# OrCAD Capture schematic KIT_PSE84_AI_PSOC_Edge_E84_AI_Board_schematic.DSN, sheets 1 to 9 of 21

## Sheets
1 20. Accessories: title: PSOC™ Edge E84 AI Board; rev: 03; note: 630-60751-01
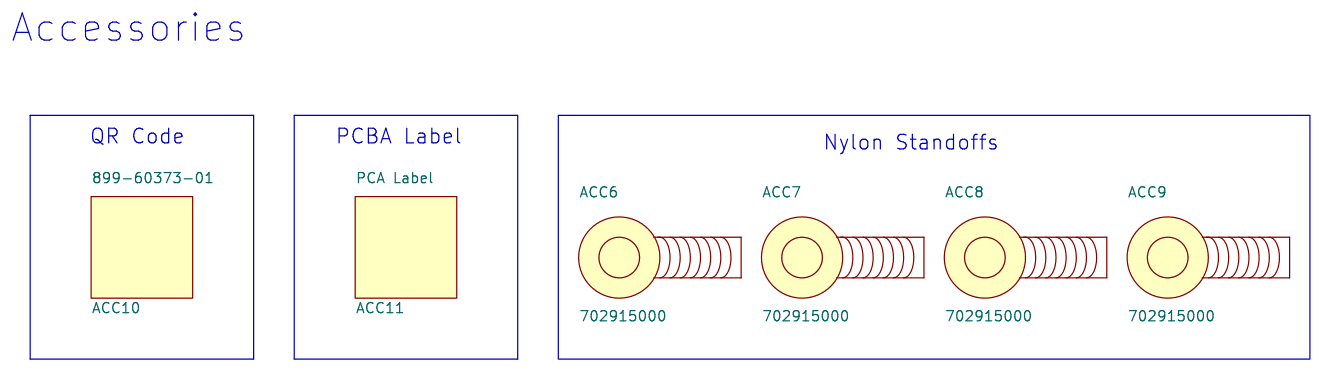
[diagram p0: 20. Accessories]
2 01. Title Page
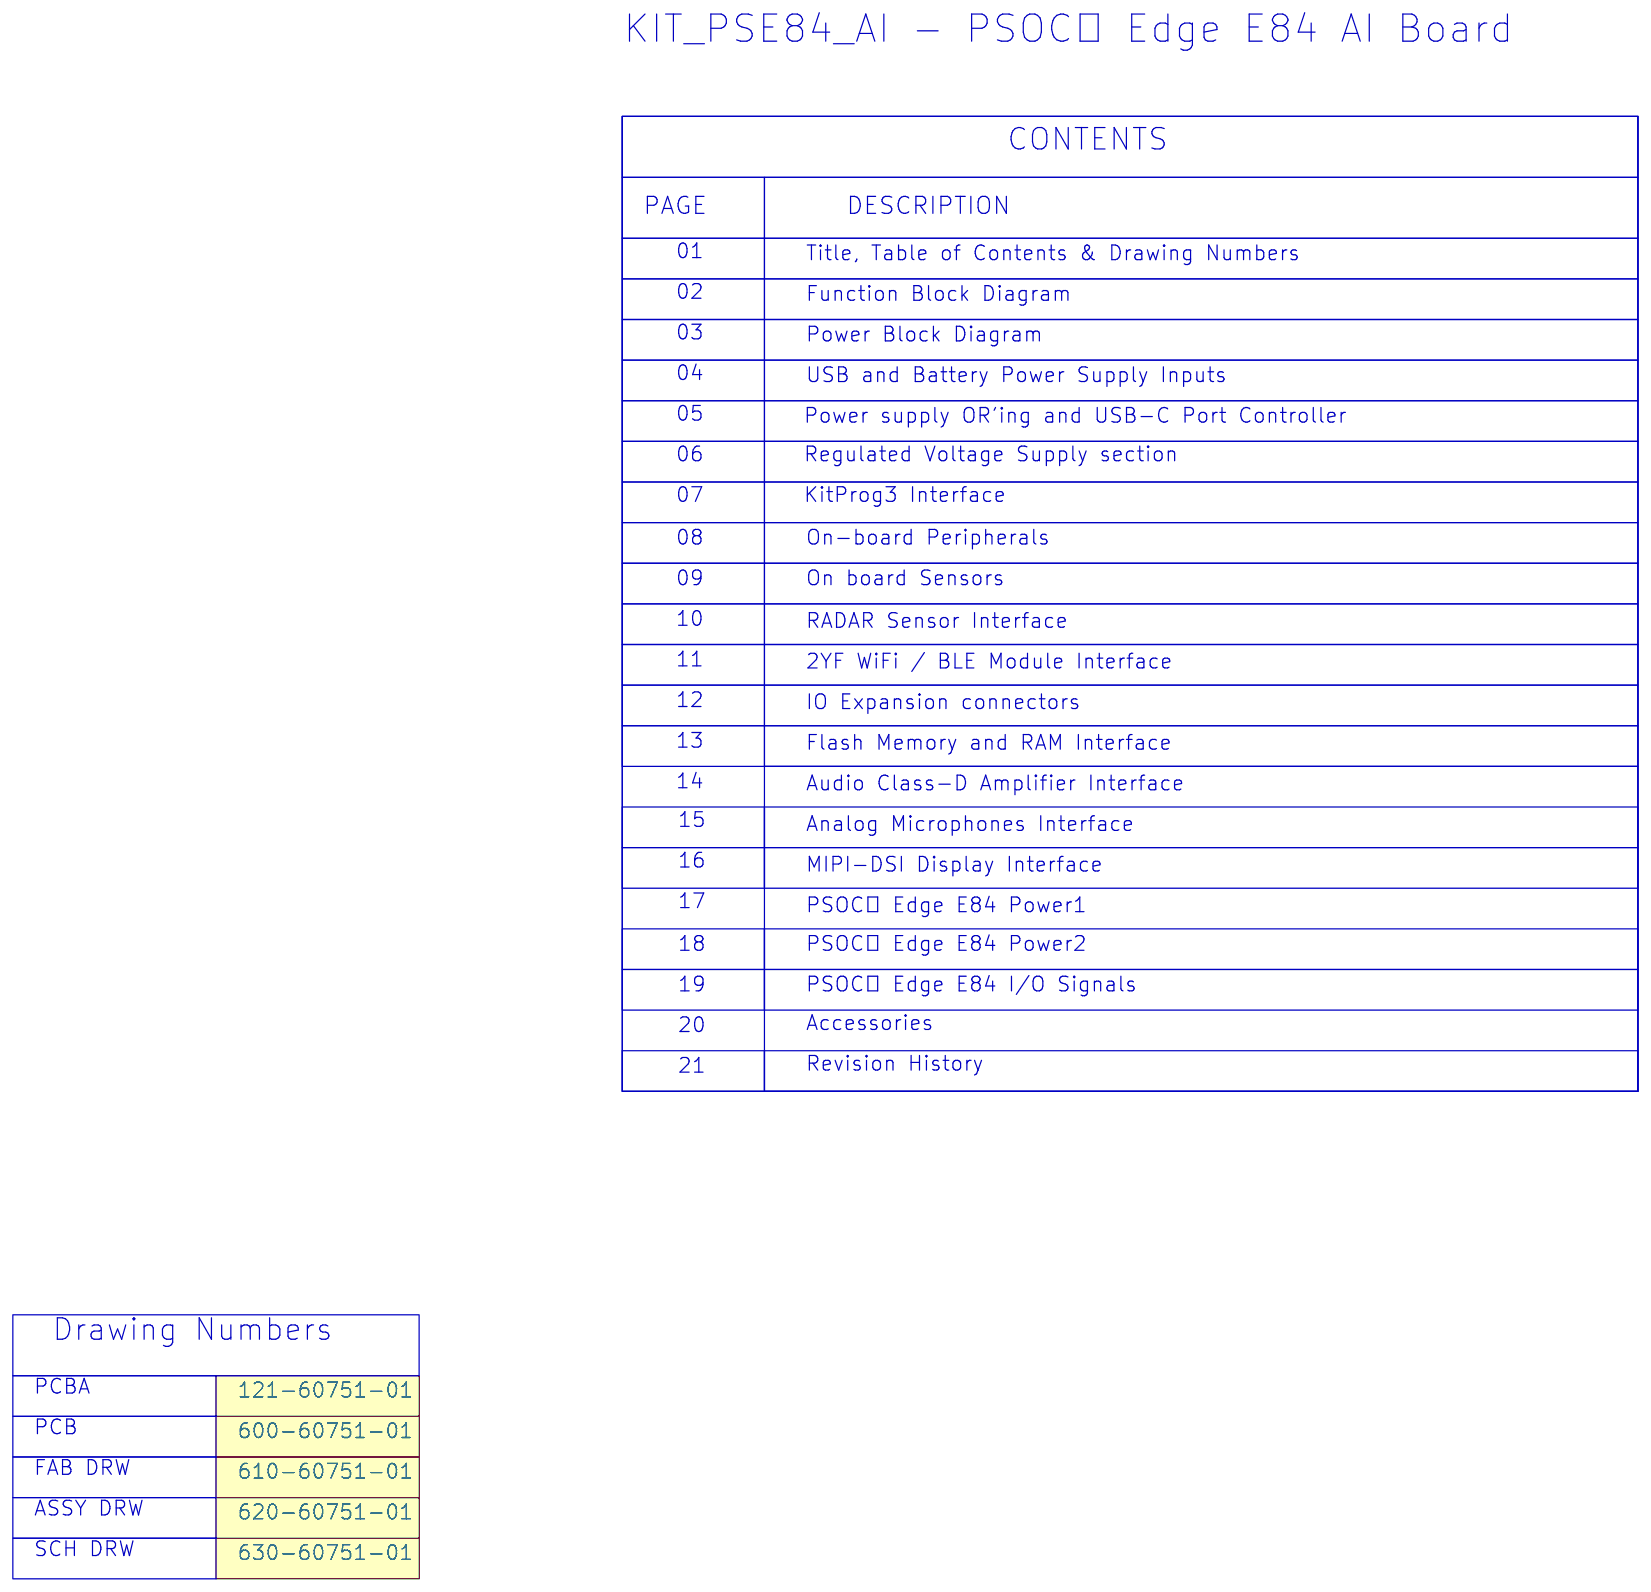
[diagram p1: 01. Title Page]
3 02. Functional Block Diagram
4 03. Power Block Diagram
5 05. Power Supply OR'ing: size A4
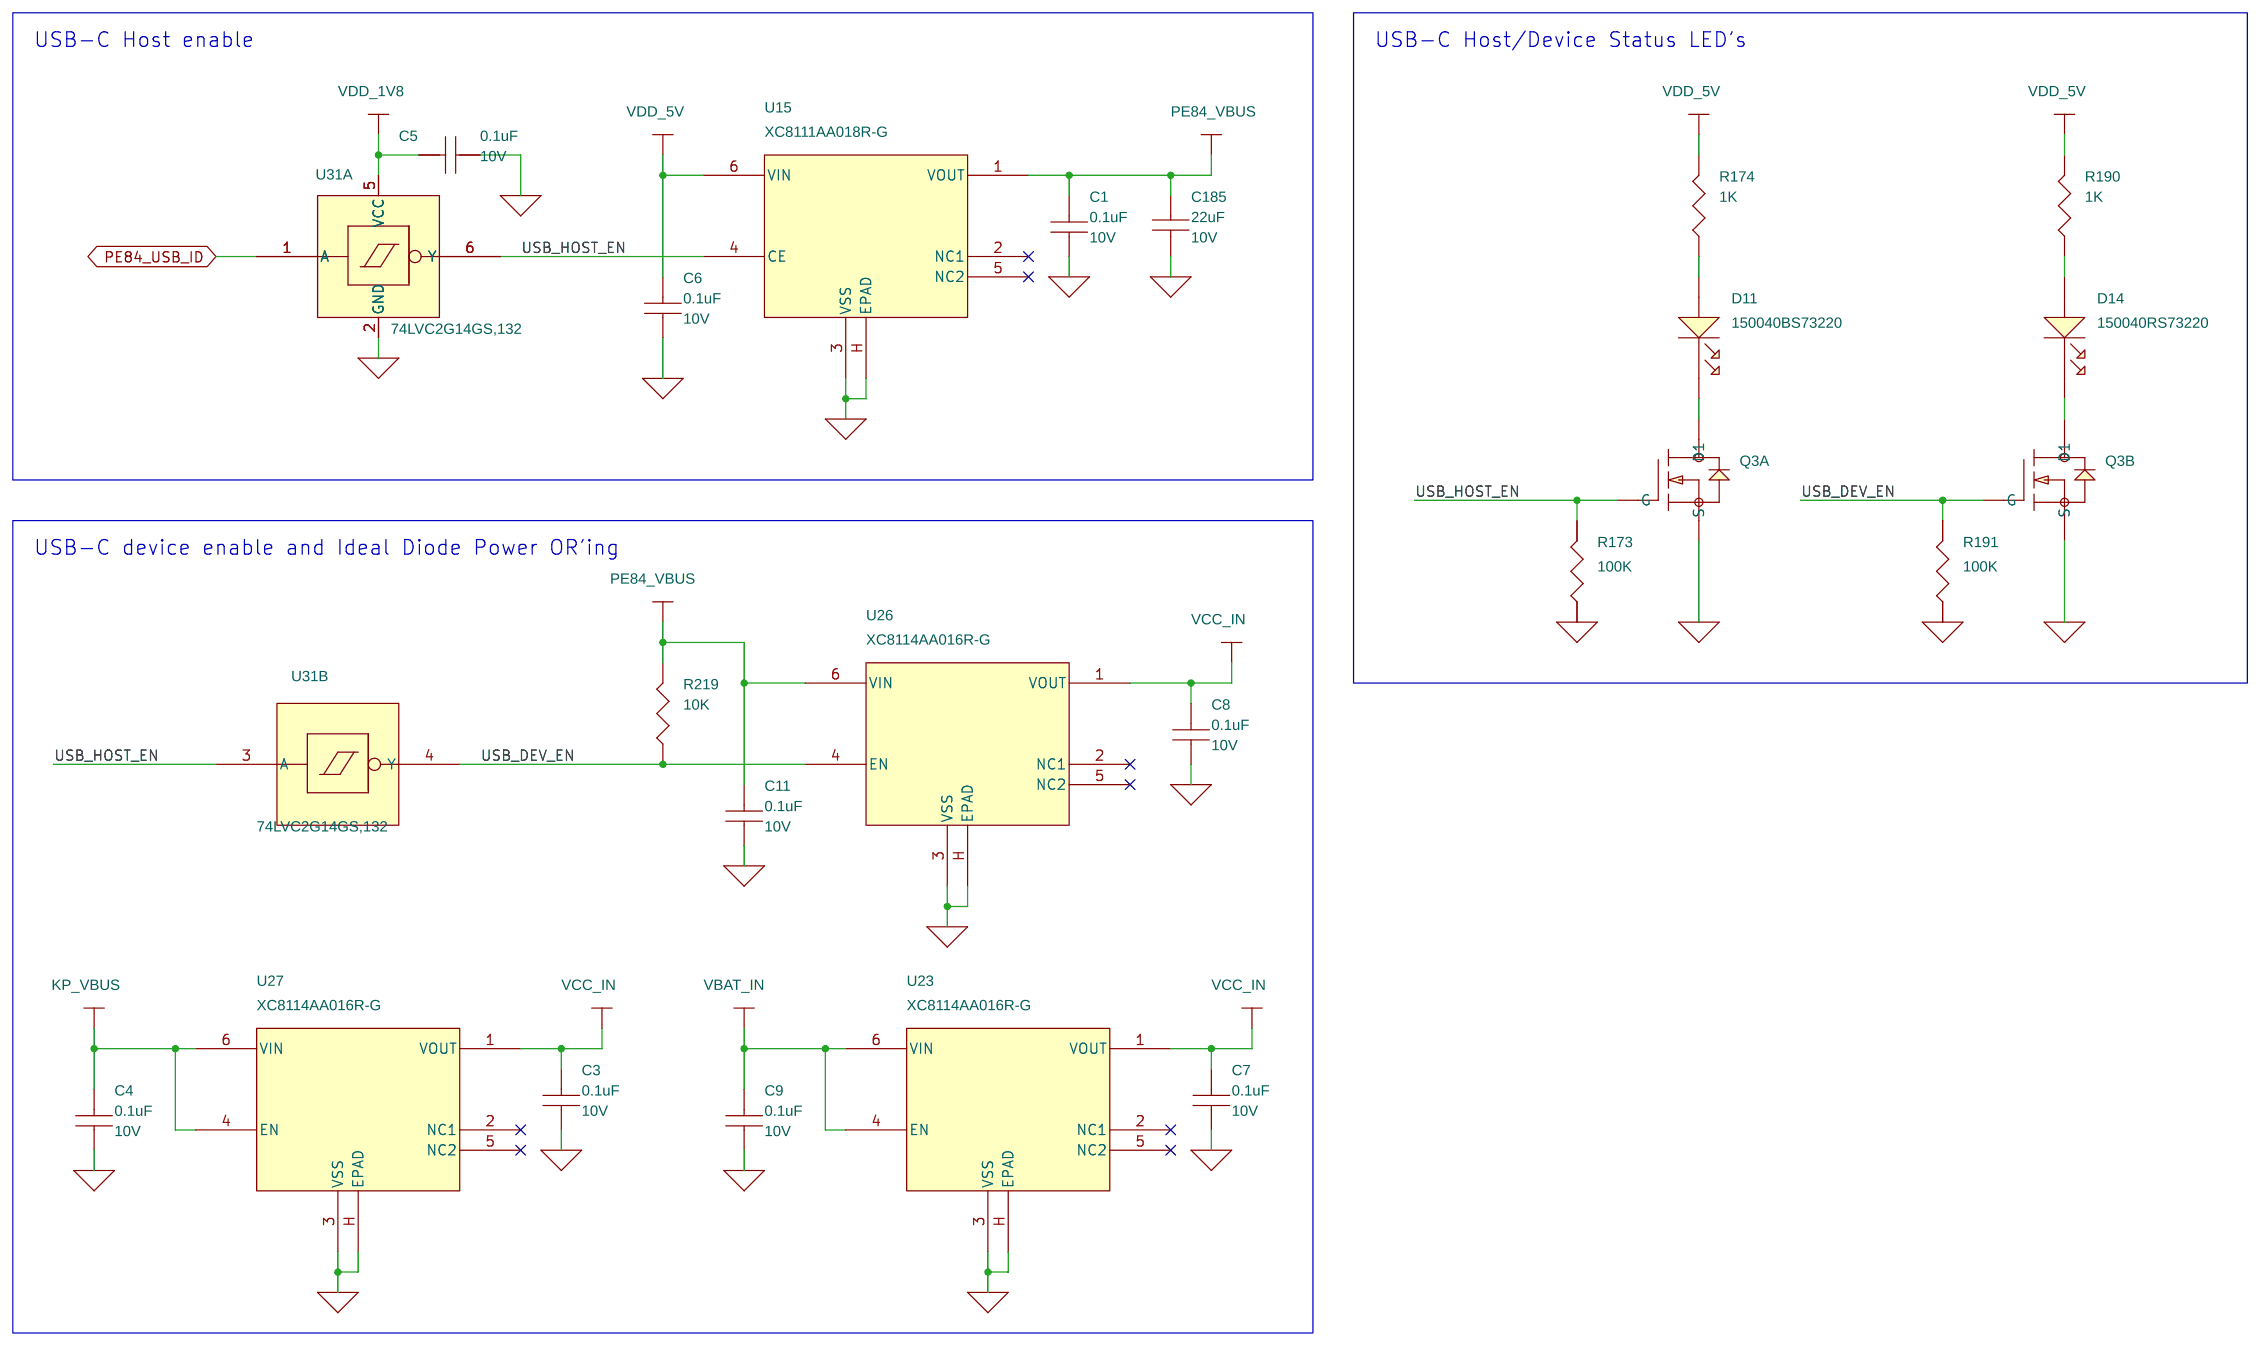
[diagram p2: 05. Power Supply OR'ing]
6 04. USB and Battery Pwr. Supply: size A4
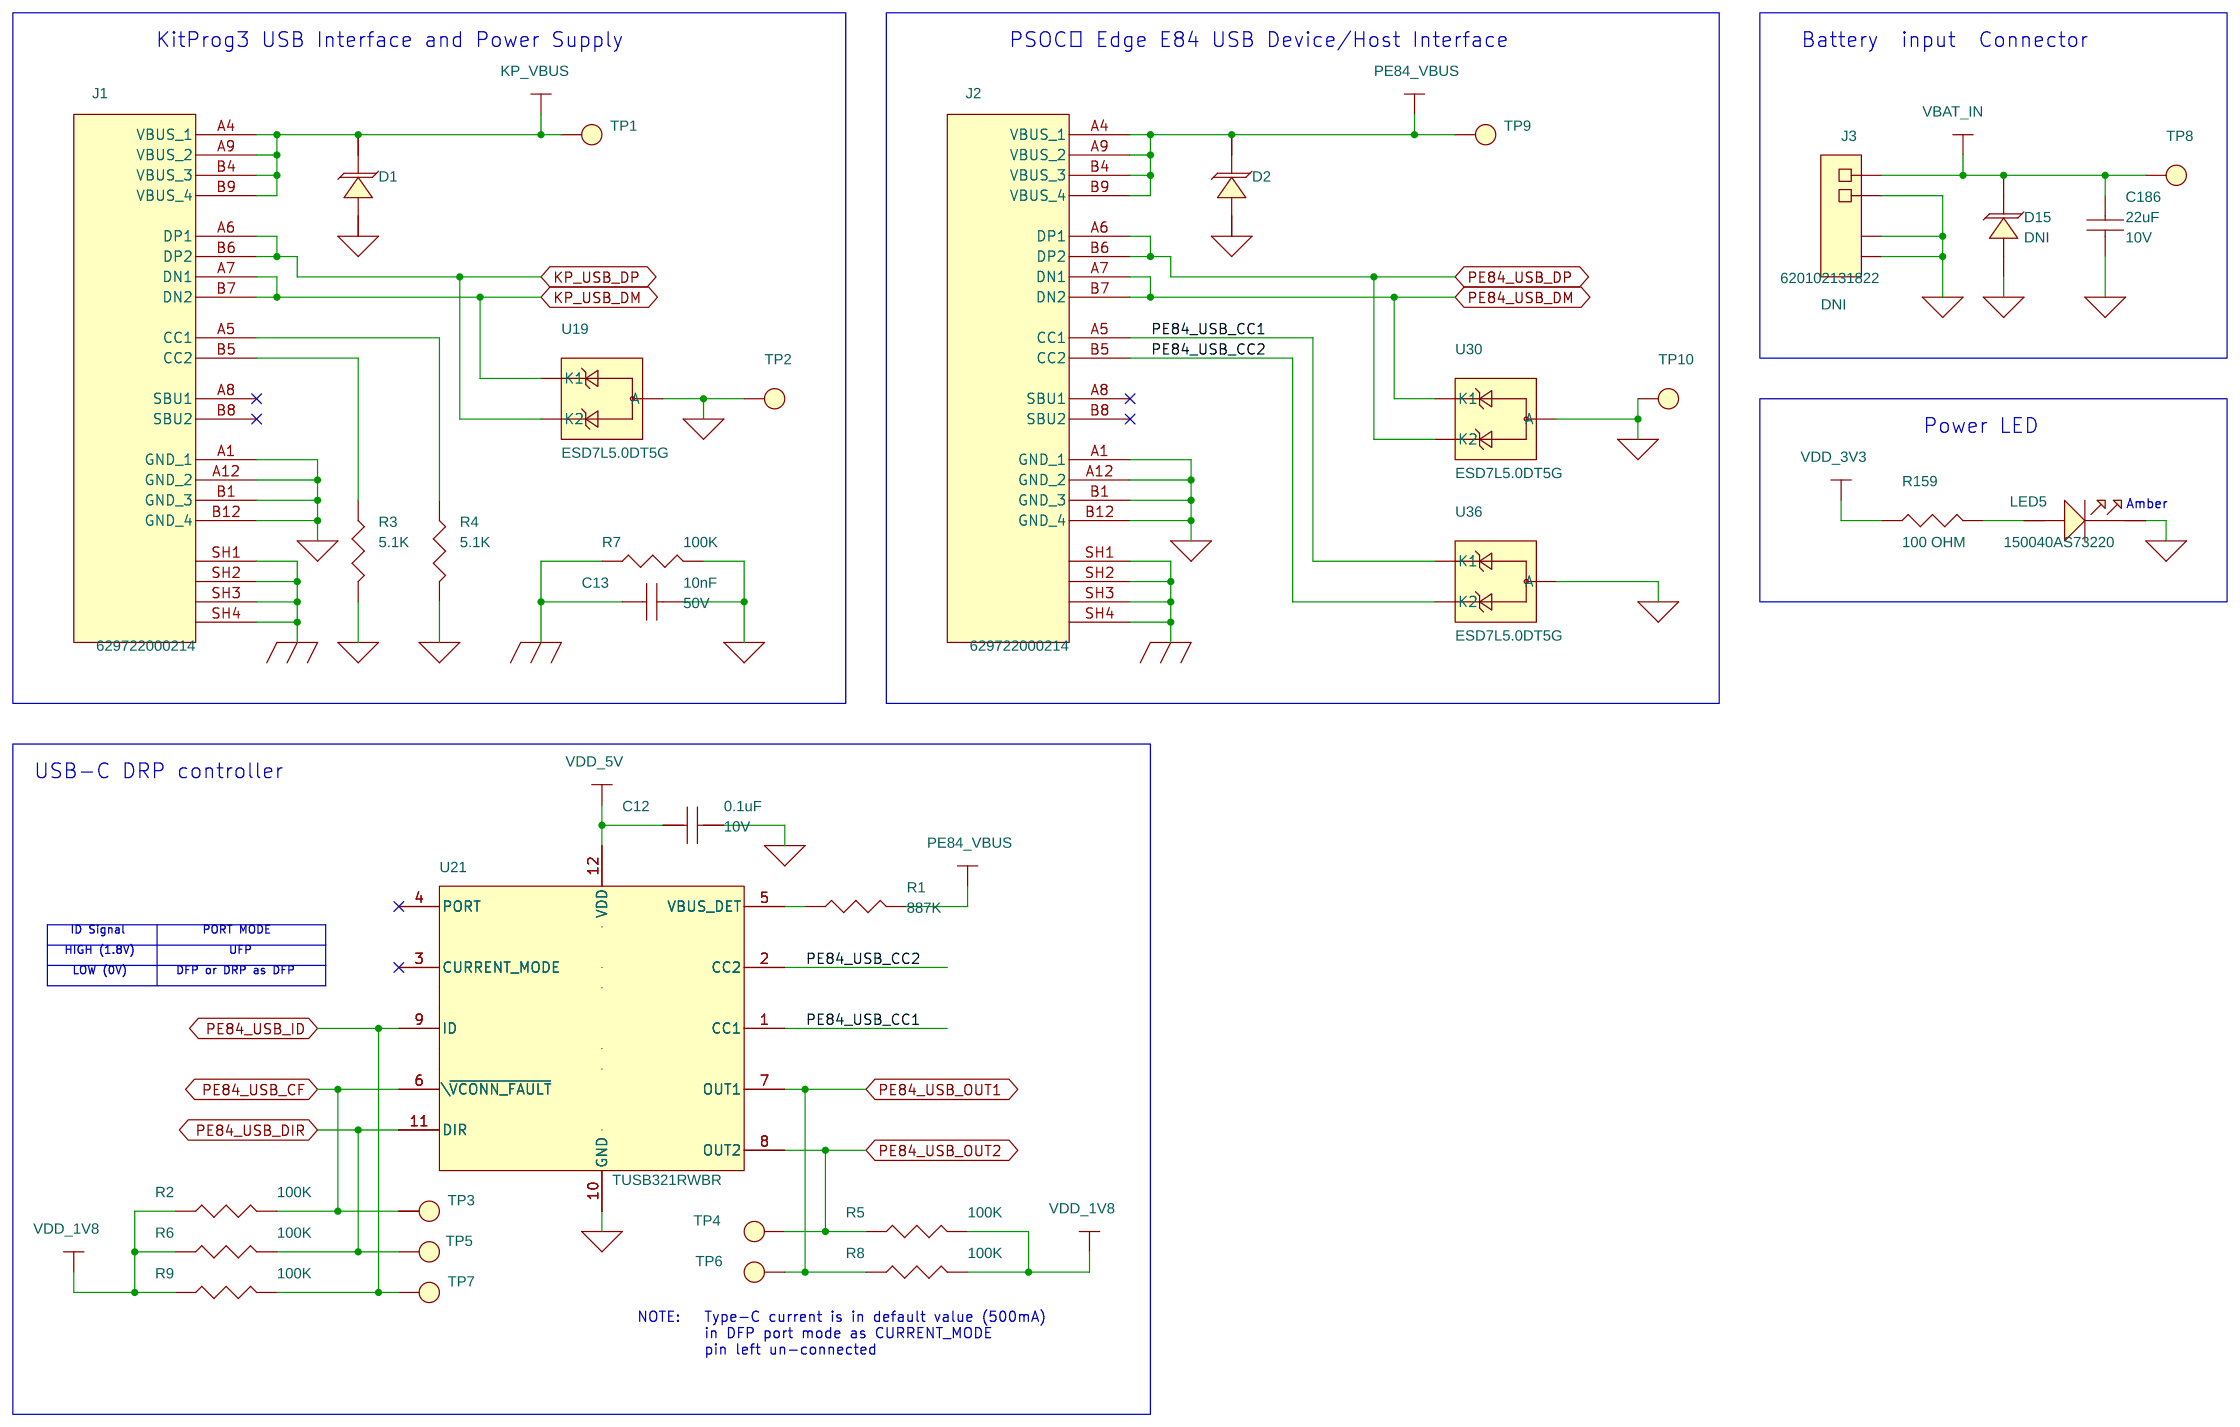
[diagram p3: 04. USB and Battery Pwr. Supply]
7 06. Regulated Voltage Supply: size A4
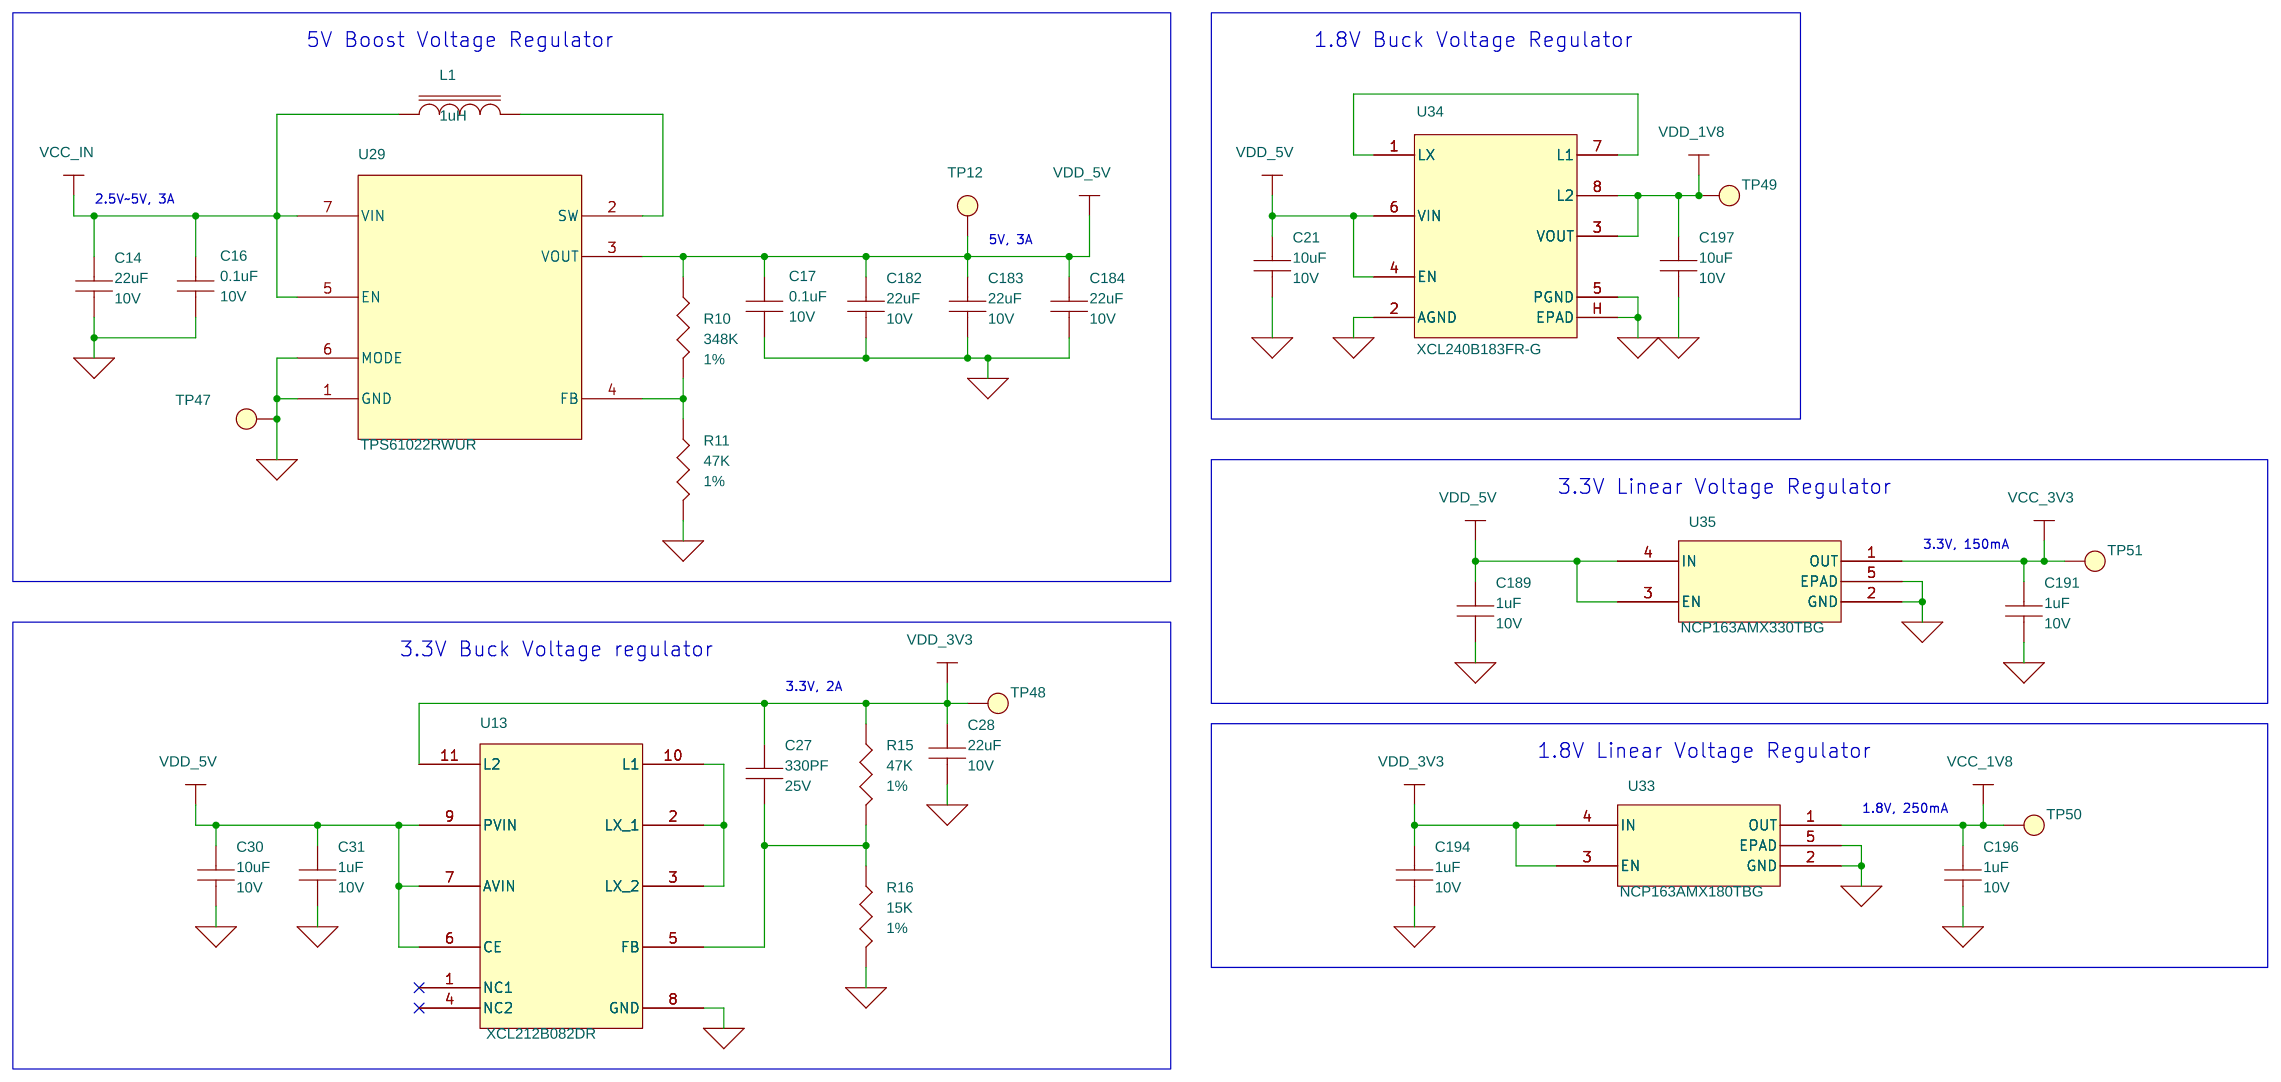
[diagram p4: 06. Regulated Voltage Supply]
8 07. KitProg3 Interface: size A4
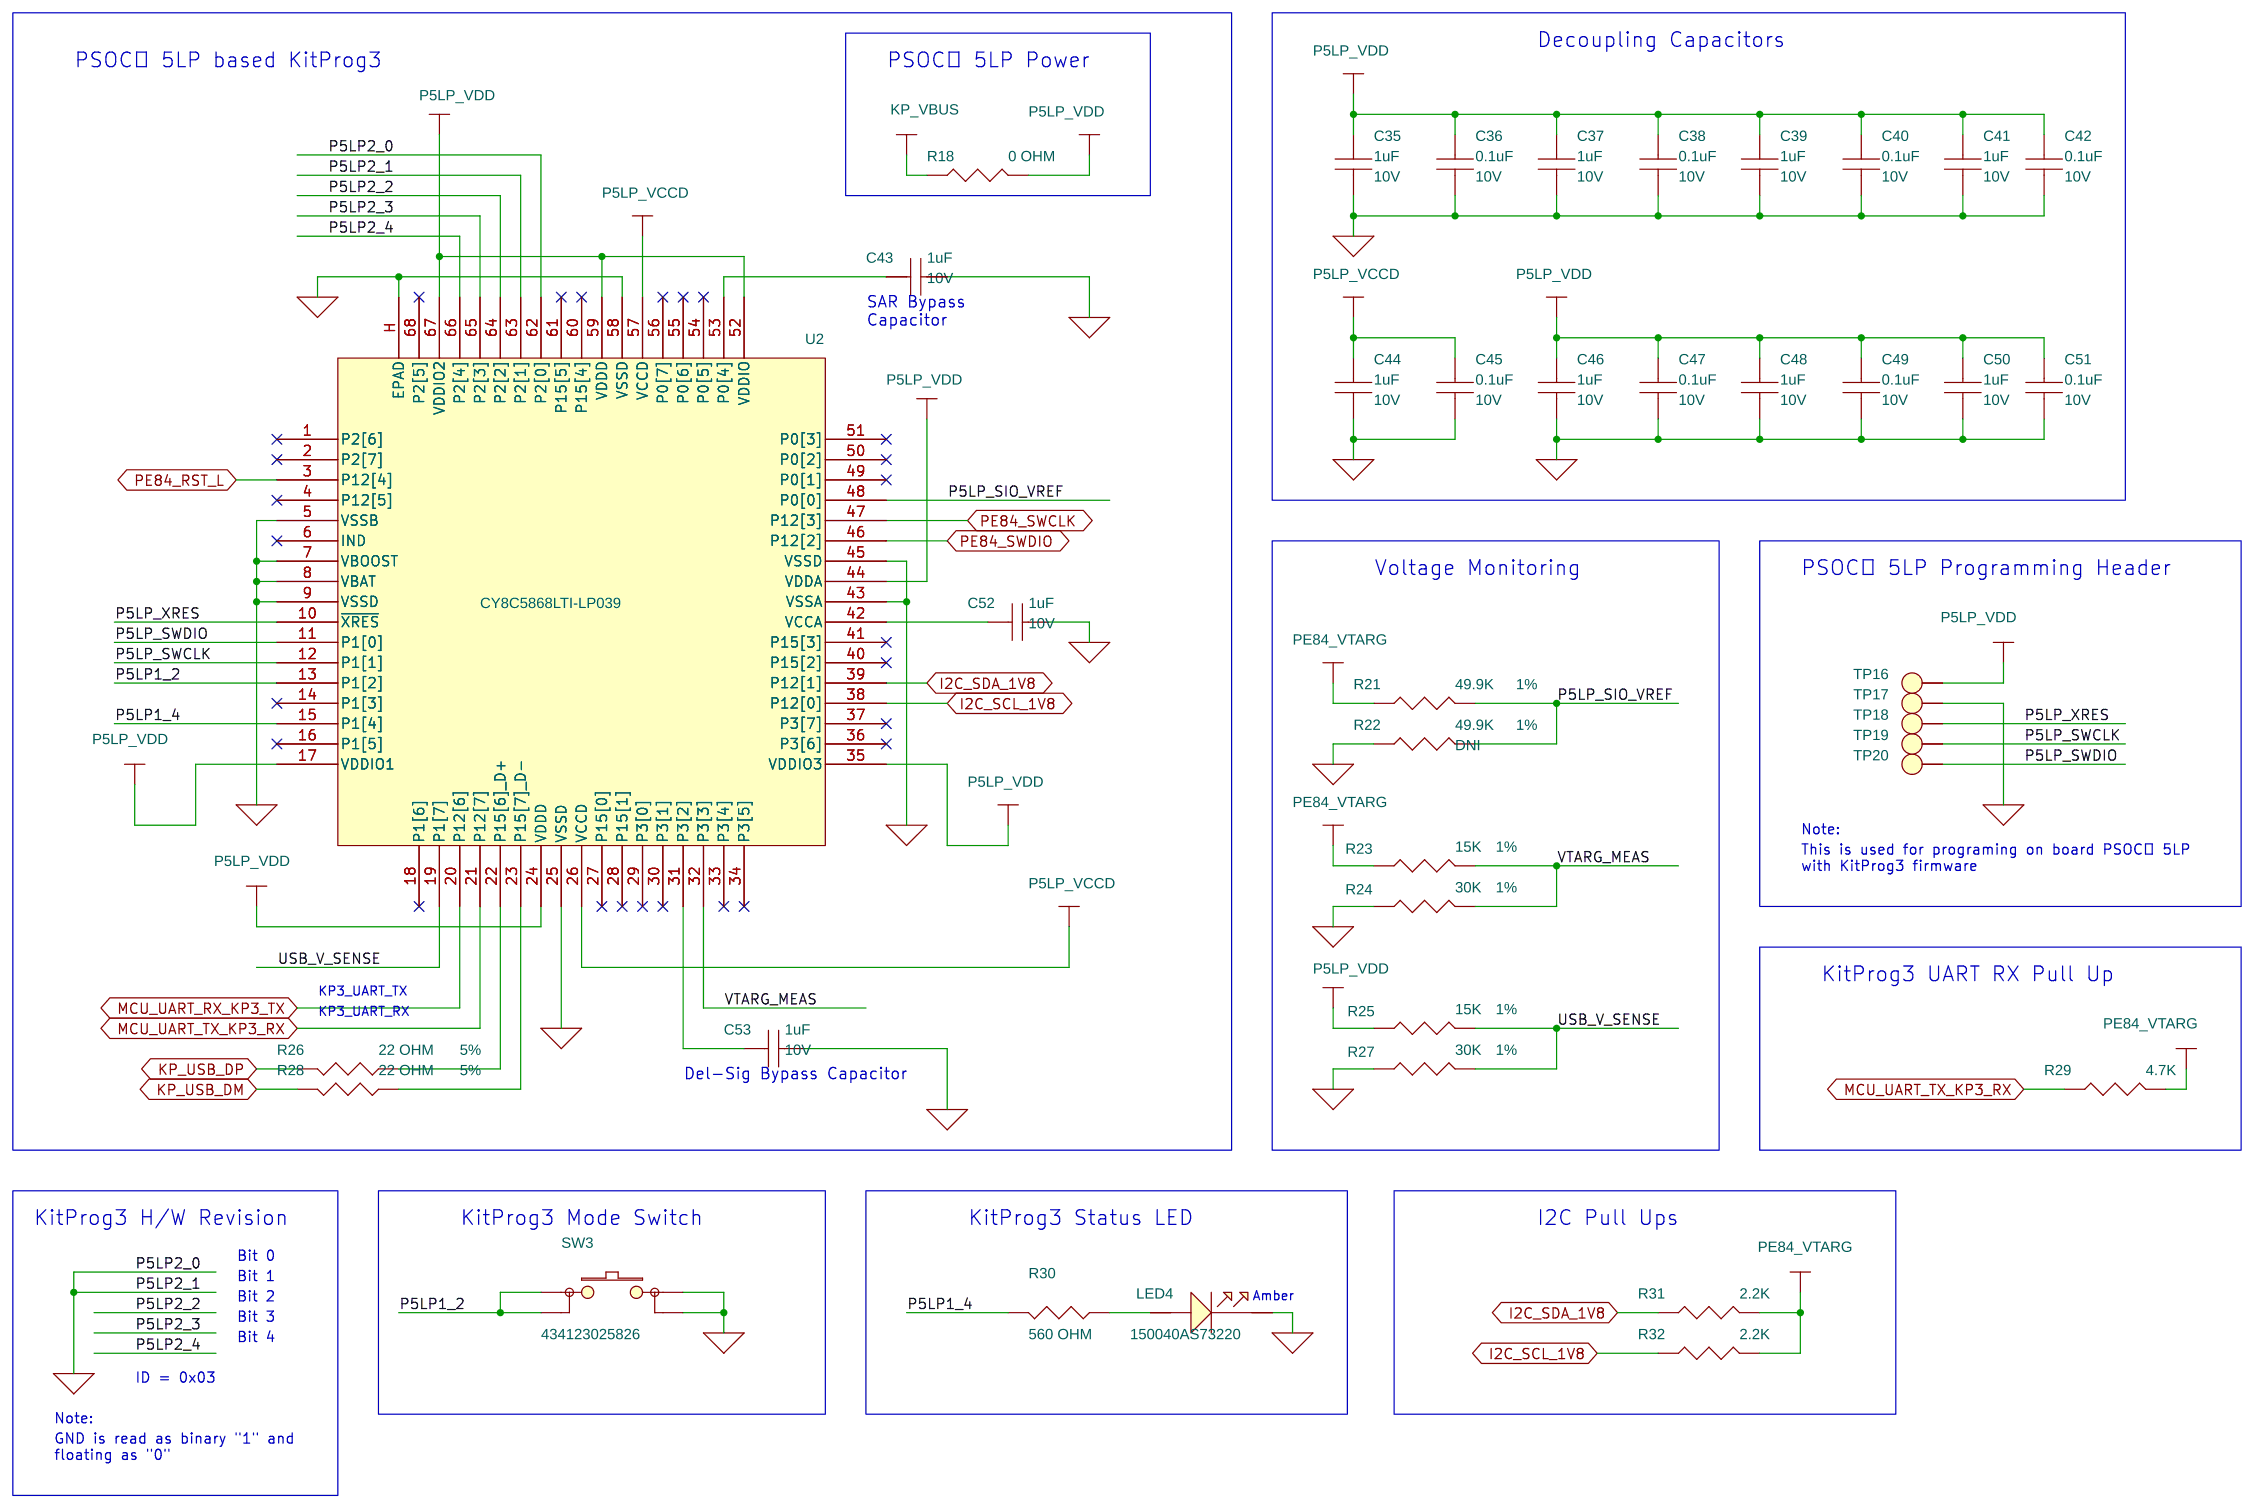
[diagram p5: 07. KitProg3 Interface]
9 08. On-Board Peripherals: size A4
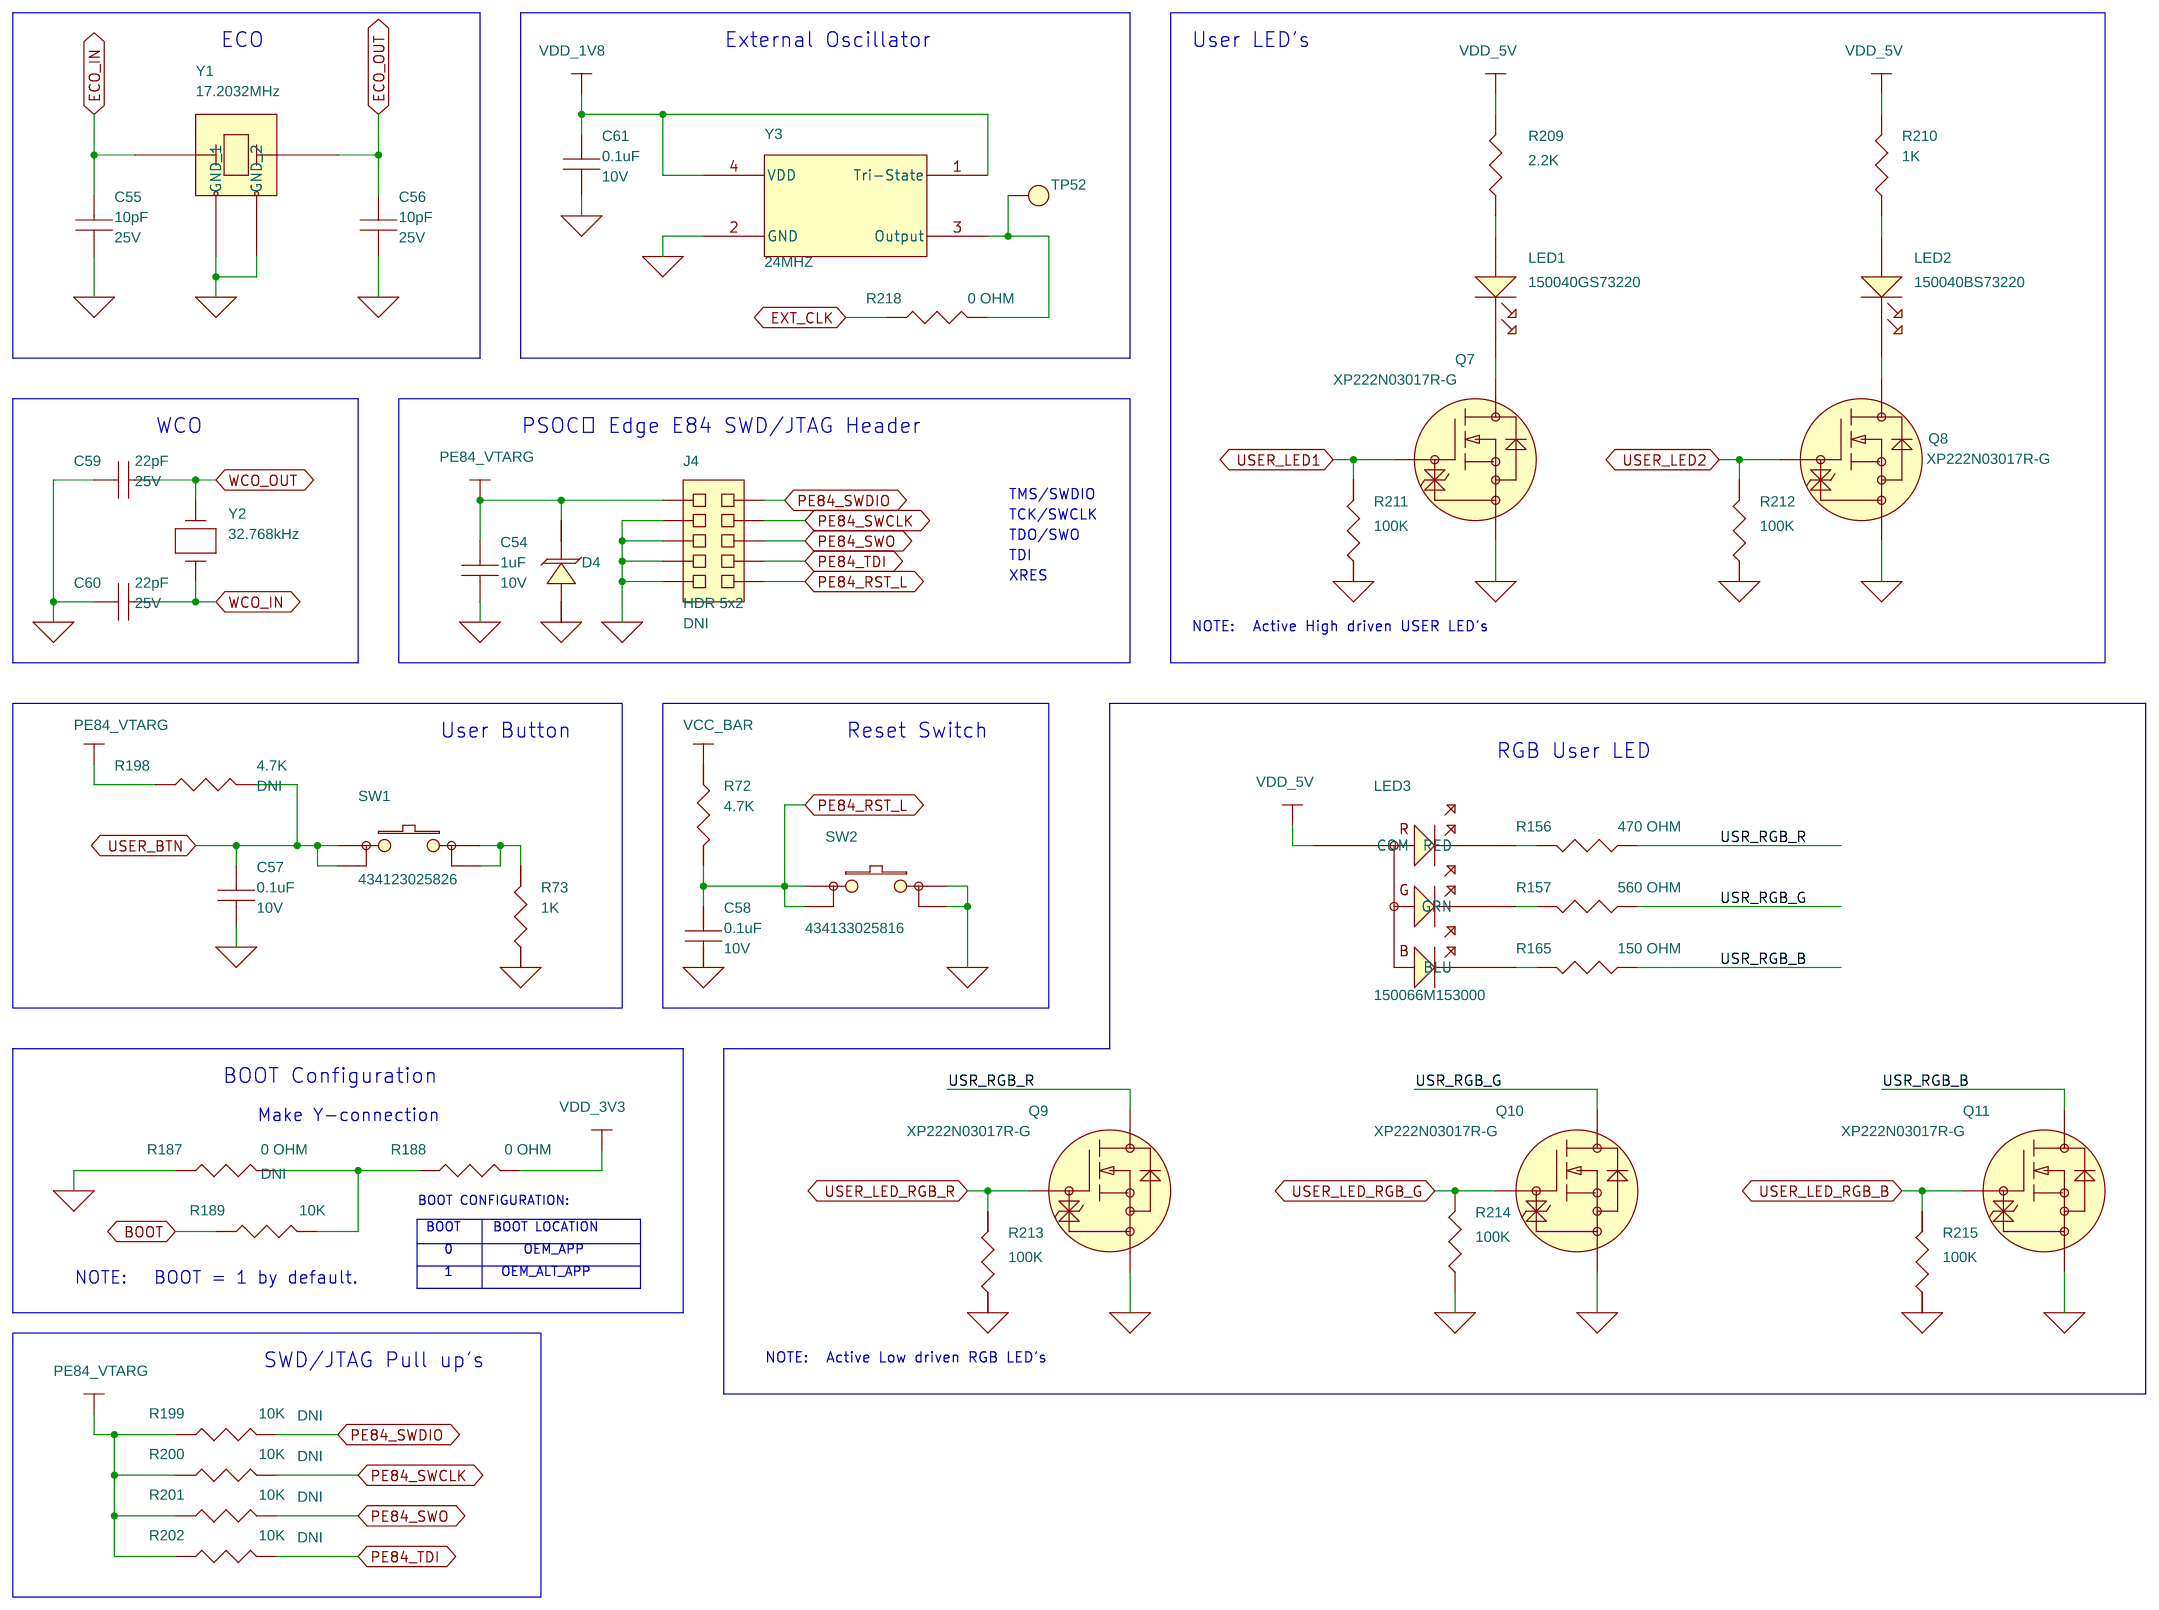
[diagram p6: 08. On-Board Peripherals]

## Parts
sheet 01. Title Page
ACC1  121-60751-01  [TBD]
ACC2  600-60751-01  [TBD]
ACC3  610-60751-01  [TBD]
ACC4  620-60751-01  [TBD]
ACC5  630-60751-01  [TBD]
sheet 04. USB and Battery Pwr. Supply
C12  0.1uF  [CAPC0603_0201N]
C13  10nF  [CAPC1005_0402N]
C186  22uF  [CAPC1005_0402N]
D1  T5V0S5A-7  [SODFL1608X77N]
D2  T5V0S5A-7  [SODFL1608X77N]
D15  T5V0S5A-7  [SODFL1608X77N]
J1  629722000214  [GCT_USB4105-GF-A]
J2  629722000214  [GCT_USB4105-GF-A]
J3  620102131822  [JST_S2B-PH-SM4-TB-LF-SN]
LED5  150040AS73220  [LEDC1005X35N_AMB_WURTH]
R1  887K  [RESC0603_0201N]
R2  100K  [RESC0603_0201N]
R3  5.1K  [RESC0603_0201N]
R4  5.1K  [RESC0603_0201N]
R5  100K  [RESC0603_0201N]
R6  100K  [RESC0603_0201N]
R7  100K  [RESC0603_0201N]
R8  100K  [RESC0603_0201N]
R9  100K  [RESC0603_0201N]
R159  100 OHM  [RESC0603_0201N]
TP1  TP_SMD  [ict_tp_smd_030rd_nsp]
TP2  TP_SMD  [ict_tp_smd_030rd_nsp]
TP3  TP_SMD  [ict_tp_smd_030rd_nsp]
TP4  TP_SMD  [ict_tp_smd_030rd_nsp]
TP5  TP_SMD  [ict_tp_smd_030rd_nsp]
TP6  TP_SMD  [ict_tp_smd_030rd_nsp]
TP7  TP_SMD  [ict_tp_smd_030rd_nsp]
TP8  TP_SMD  [ict_tp_smd_030rd_nsp]
TP9  TP_SMD  [ict_tp_smd_030rd_nsp]
TP10  TP_SMD  [ict_tp_smd_030rd_nsp]
U19  ESD7L5.0DT5G  [SOTFL40P120X59-3N]
U21  TUSB321RWBR  [X2QFN40P160X160X40-12N_TI]
U30  ESD7L5.0DT5G  [SOTFL40P120X59-3N]
U36  ESD7L5.0DT5G  [SOTFL40P120X59-3N]
sheet 05. Power Supply OR'ing
C1  0.1uF  [CAPC0603_0201N]
C3  0.1uF  [CAPC0603_0201N]
C4  0.1uF  [CAPC0603_0201N]
C5  0.1uF  [CAPC0603_0201N]
C6  0.1uF  [CAPC0603_0201N]
C7  0.1uF  [CAPC0603_0201N]
C8  0.1uF  [CAPC0603_0201N]
C9  0.1uF  [CAPC0603_0201N]
C11  0.1uF  [CAPC0603_0201N]
C185  22uF  [CAPC1005_0402N]
D11  150040BS73220  [LEDC1005X35N_AMB_WURTH]
D14  150040RS73220  [LEDC1005X35N_AMB_WURTH]
Q3  BSD840NH6327XTSA1  [SOT65P210X100-6M]  (sections A,B)
R173  100K  [RESC0603_0201N]
R174  1K  [RESC0603_0201N]
R190  1K  [RESC0603_0201N]
R191  100K  [RESC0603_0201N]
R219  10K  [RESC0603_0201N]
U15  XC8111AA018R-G  [XFDFN50P180X150X33-7N_TOREX]
U23  XC8114AA016R-G  [SON50P200X180X60-6N_TP]
U26  XC8114AA016R-G  [SON50P200X180X60-6N_TP]
U27  XC8114AA016R-G  [SON50P200X180X60-6N_TP]
U31  74LVC2G14GS,132  [DFN35P100X100X40-6N]  (sections A,B)
sheet 06. Regulated Voltage Supply
C14  22uF  [CAPC1005_0402N]
C16  0.1uF  [CAPC0603_0201N]
C17  0.1uF  [CAPC0603_0201N]
C21  10uF  [CAPC1005_0402N]
C27  330PF  [CAPC0603_0201N]
C28  22uF  [CAPC1005_0402N]
C30  10uF  [CAPC1005_0402N]
C31  1uF  [CAPC0603_0201N]
C182  22uF  [CAPC1005_0402N]
C183  22uF  [CAPC1005_0402N]
C184  22uF  [CAPC1005_0402N]
C189  1uF  [CAPC1005_0402N]
C191  1uF  [CAPC1005_0402N]
C194  1uF  [CAPC1005_0402N]
C196  1uF  [CAPC1005_0402N]
C197  10uF  [CAPC1005_0402N]
L1  1uH  [IND_74438336010]
R10  348K  [RESC0603_0201N]
R11  47K  [RESC0603_0201N]
R15  47K  [RESC0603_0201N]
R16  15K  [RESC0603_0201N]
TP12  TP_SMD  [ict_tp_smd_030rd_nsp]
TP47  TP_SMD  [ict_tp_smd_030rd_nsp]
TP48  TP_SMD  [ict_tp_smd_030rd_nsp]
TP49  TP_SMD  [ict_tp_smd_030rd_nsp]
TP50  TP_SMD  [ict_tp_smd_030rd_nsp]
TP51  TP_SMD  [ict_tp_smd_030rd_nsp]
U13  XCL212B082DR  [CONV_XCL212B082DR]
U29  TPS61022RWUR  [VQFN50P200X200X100-7N_TI]
U33  NCP163AMX180TBG  [DFN65P100X100X43-5N]
U34  XCL240B183FR-G  [CONV_XCL240B183FR-G]
U35  NCP163AMX330TBG  [DFN65P100X100X43-5N]
sheet 07. KitProg3 Interface
C35  1uF  [CAPC0603_0201N]
C36  0.1uF  [CAPC0603_0201N]
C37  1uF  [CAPC0603_0201N]
C38  0.1uF  [CAPC0603_0201N]
C39  1uF  [CAPC0603_0201N]
C40  0.1uF  [CAPC0603_0201N]
C41  1uF  [CAPC0603_0201N]
C42  0.1uF  [CAPC0603_0201N]
C43  1uF  [CAPC0603_0201N]
C44  1uF  [CAPC0603_0201N]
C45  0.1uF  [CAPC0603_0201N]
C46  1uF  [CAPC0603_0201N]
C47  0.1uF  [CAPC0603_0201N]
C48  1uF  [CAPC0603_0201N]
C49  0.1uF  [CAPC0603_0201N]
C50  1uF  [CAPC0603_0201N]
C51  0.1uF  [CAPC0603_0201N]
C52  1uF  [CAPC0603_0201N]
C53  1uF  [CAPC0603_0201N]
LED4  150040AS73220  [LEDC1005X35N_AMB_WURTH]
R18  0 OHM  [RESC1005_0402N]
R21  49.9K  [RESC0603_0201N]
R22  49.9K  [RESC0603_0201N]
R23  15K  [RESC0603_0201N]
R24  30K  [RESC0603_0201N]
R25  15K  [RESC0603_0201N]
R26  22 OHM  [RESC0603_0201N]
R27  30K  [RESC0603_0201N]
R28  22 OHM  [RESC0603_0201N]
R29  4.7K  [RESC0603_0201N]
R30  560 OHM  [RESC1005_0402N]
R31  2.2K  [RESC0603_0201N]
R32  2.2K  [RESC0603_0201N]
SW3  434123025826  [SW_SKRPACE010]
TP16  TP_SMD  [ict_tp_smd_030rd_nsp]
TP17  TP_SMD  [ict_tp_smd_030rd_nsp]
TP18  TP_SMD  [ict_tp_smd_030rd_nsp]
TP19  TP_SMD  [ict_tp_smd_030rd_nsp]
TP20  TP_SMD  [ict_tp_smd_030rd_nsp]
U2  CY8C5868LTI-LP039  [QFN40P800X800_68-H580N]
sheet 08. On-Board Peripherals
C54  1uF  [CAPC0603_0201N]
C55  10pF  [CAPC0603_0201N]
C56  10pF  [CAPC0603_0201N]
C57  0.1uF  [CAPC0603_0201N]
C58  0.1uF  [CAPC0603_0201N]
C59  22pF  [CAPC0603_0201N]
C60  22pF  [CAPC0603_0201N]
C61  0.1uF  [CAPC0603_0201N]
D4  ESD5V0D5-TP  [SODFL1608X77N]
J4  HDR 5x2  [SAMT_FTSH-105-XX-X-DV-K]
LED1  150040GS73220  [LEDC1005X35N_AMB_WURTH]
LED2  150040BS73220  [LEDC1005X35N_AMB_WURTH]
LED3  150066M153000  [LED_150066M153000]
Q7  XP222N03017R-G  [SOTFL40P120X50-3N_MOSFET_TOREX]
Q8  XP222N03017R-G  [SOTFL40P120X50-3N_MOSFET_TOREX]
Q9  XP222N03017R-G  [SOTFL40P120X50-3N_MOSFET_TOREX]
Q10  XP222N03017R-G  [SOTFL40P120X50-3N_MOSFET_TOREX]
Q11  XP222N03017R-G  [SOTFL40P120X50-3N_MOSFET_TOREX]
R72  4.7K  [RESC0603_0201N]
R73  1K  [RESC0603_0201N]
R156  470 OHM  [RESC1005_0402N]
R157  560 OHM  [RESC1005_0402N]
R165  150 OHM  [RESC1005_0402N]
R187  0 OHM  [RESC1608_0603N]
R188  0 OHM  [RESC1608_0603N]
R189  10K  [RESC0603_0201N]
R198  4.7K  [RESC0603_0201N]
R199  10K  [RESC0603_0201N]
R200  10K  [RESC0603_0201N]
R201  10K  [RESC0603_0201N]
R202  10K  [RESC0603_0201N]
R209  2.2K  [RESC0603_0201N]
R210  1K  [RESC0603_0201N]
R211  100K  [RESC0603_0201N]
R212  100K  [RESC0603_0201N]
R213  100K  [RESC0603_0201N]
R214  100K  [RESC0603_0201N]
R215  100K  [RESC0603_0201N]
R218  0 OHM  [RESC1005_0402N]
SW1  434123025826  [SW_SKRPACE010]
SW2  434133025816  [SW_434133025816]
TP52  TP_SMD  [ict_tp_smd_030rd_nsp]
Y1  17.2032MHz  [XTALS4_2MX1M6]
Y2  32.768kHz  [XTAL_ABS05_1M6X1M]
Y3  24MHZ  [OSCCC200X250X90-4N]
sheet 20. Accessories
ACC6  702915000  [TBD]
ACC7  702915000  [TBD]
ACC8  702915000  [TBD]
ACC9  702915000  [TBD]
ACC10  899-60373-01  [TBD]
ACC11  PCA Label  [TBD]

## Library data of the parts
ACC1 = PCB: ASSY, PCBA, KIT_PSE84_AI - PSOC™ Edge E84 AI Board; Dist_Part_Number: -NA-; Distributor: -NA-; Manufacturer: Cypress Approved CM; Mfr_Name: Cypress Approved CM; Sub_Allowed: NO
ACC2 = PCB: PCB, BARE, KIT_PSE84_AI - PSOC™ Edge E84 AI Board; Dist_Part_Number: -NA-; Distributor: -NA-; Manufacturer: Cypress Approved CM; Mfr_Name: Cypress Approved CM; Sub_Allowed: NO
ACC3 = PCB: DRW, FABRICATION DRAWING, KIT_PSE84_AI - PSOC™ Edge E84 AI Board; Dist_Part_Number: -NA-; Distributor: -NA-; Manufacturer: -NA-; Mfr_Name: -NA-; Sub_Allowed: NO
ACC4 = PCB: DRW, ASSEMBLY DRAWING, KIT_PSE84_AI - PSOC™ Edge E84 AI Board; Dist_Part_Number: -NA-; Distributor: -NA-; Manufacturer: -NA-; Mfr_Name: -NA-; Sub_Allowed: NO
ACC5 = PCB: DRW, SCHEMATIC DRAWING, KIT_PSE84_AI - PSOC™ Edge E84 AI Board; Dist_Part_Number: -NA-; Distributor: -NA-; Manufacturer: -NA-; Mfr_Name: -NA-; Sub_Allowed: NO
C1 C3-C9 C11 C12 C36 C38 C40 C42 C45 C47 C49 C51 C58 = CAP-NP: CAP, CER, 0.1uF, 10%, X5R, 10V, 0201; Approved: Approved; CY_PN: 510-60777-01; Device File: 510-60330-01; Device_File: 510-60777-01; Dielectric: X5R; FPLIST: CAPC0603_0201N,CAPC0603_0201Q; Lifecycle: Active; Manufacturer: Wurth; Manufacturer_PN: 885012104002; Operating_Temp: -55°C ~ 85°C; Package: 0201; Part Status: In Prod; Part_Status: In Prod; Tolerance: 0.1; Voltage: 10V
C13 = CAP-NP: CAP, CER, 10nF, 10%, X7R, 50V, 0402; Approved: Approved; CY_PN: 510-60089-01; Device_File: 510-60089-01; Dielectric: X7R; FPLIST: CAPC1005_0402N,CAPC1005_0402M; Lifecycle: Active; Manufacturer: Wurth; Manufacturer_PN: 885012205067; Operating_Temp: - 55 C to + 125 C; Package: 0402; Part_Status: In Prod; Tolerance: 10%; Voltage: 50V
C14 C28 C182-C186 = CAP-NP: CAP, CER, 22uF, 20%, X5R, 10V, 0402; Approved: Approved; CY_PN: 510-61184-01; Device_File: 510-61184-01; Dielectric: X5R; FPLIST: CAPC1005_0402N,CAPC1005_0402M; Lifecycle: Active; Manufacturer: Murata; Manufacturer_PN: GRM158R61A226ME15D; Operating_Temp: -55°C ~ 85°C; Package: 0402; Part_Status: Unrel; Tolerance: 20%; Voltage: 10V
D1 D2 = DIO-TVS: DIODE, TVS, 17.3V, 15A, SOD-523; Approved: Approved; CY_PN: 530-60314-01; Device_File: 530-60314-01; Lifecycle: Active; Manufacturer: Diodes Incorporated; Operating_Temp: -65°C ~ 150°C; Package: SOD-523; Part_Status: Unrel; Rating: 15A; Voltage: 17.3V
D15 = DIO-TVS: DIODE, TVS, 17.3V, 15A, SOD-523; Approved: Approved; CY_PN: 530-60314-01; DNI: DNI; Device_File: 530-60314-01; Lifecycle: Active; Manufacturer: Diodes Incorporated; Operating_Temp: -65°C ~ 150°C; Package: SOD-523; Part_Status: Unrel; Rating: 15A; Voltage: 17.3V
J1 J2 = USB_TYPE_C-16PIN_4SH: CONN, RCPT, USB, TYPE-C, USB2.0, 12POS, TOP MOUNT, RA, SMD; Approved: Approved; CY_PN: 720-60675-01; Conatct_Length: NA; Contact_Finish: GOLD; Current_Rating: 5A; Device_File: 720-60675-01; Lifecycle: Active; Manufacturer: Wurth; Mated_Height: NA; Operating_Temp: -40°C to +85°C; Part_Status: In Prod; Pin_Pitch: NA; Pins: 12; Row_pitch: NA; Rows: 1; Shrouding: NA
J3 = PLG-2-J_SH1_2: CONN, HDR, 1x2POS, SHROUNDED, R/A, 2MM PITCH, SMT; Approved: Approved; CY_PN: 720-60595-01; Conatct_Length: NA; Contact_Finish: Tin; Current_Rating: 2A; DNI: DNI; Device_File: 720-60595-01; Lifecycle: Active; Manufacturer: Wurth; Mated_Height: NA; Operating_Temp: -40°C ~ 85°C; Part_Status: In Des; Pin_Pitch: 2mm; Pins: 2; Row_pitch: NA; Rows: 1; Shrouding: Shrouded
LED4 LED5 = DIO-LED: LED, AMBER, CLEAR, 605nm, 2V, 0402; Approved: Approved; CY_PN: 534-60152-01; Device_File: 534-60152-01; Lifecycle: Active; Manufacturer: WURTH; Operating_Temp: -40°C ~ 85°C; Package: 0402; Part_Status: Unrel; Rating: 20mA; Voltage: 2V
R1 = RES: RES, FIXED, 887K OHM, 1%, 1/20W, 0201; Approved: Approved; CY_PN: 500-61426-01; Device_File: 500-61426-01; FPLIST: RESC0603_0201N,RESC0603_0201Q; Lifecycle: Active; Manufacturer: Panasonic; Manufacturer_PN: ERJ-1GNF8873C; Operating_Temp: -55°C ~ 125°C; Package: 0201; Part_Status: unrel; Rating: 1/20W; Tolerance: 1%
R2 R5 R6 R8 R9 R173 R191 R211-R215 = RES: RES, 100K OHM, 1%, 1/20W, 0201; Approved: Approved; CY_PN: 500-61334-01; Device_File: 500-61334-01; FPLIST: RESC0603_0201N,RESC0603_0201Q; Lifecycle: Active; Manufacturer: Yageo; Manufacturer_PN: RC0201FR-07100KL; Operating_Temp: -55°C ~ 125°C; Package: 0201; Part_Status: In Des; Rating: 1/20W; Tolerance: 1%
R3 R4 = RES: RES, 5.1K OHM, 5%, 1/20W, 0201; Approved: Approved; CY_PN: 500-61333-01; Device_File: 500-61333-01; FPLIST: RESC0603_0201N,RESC0603_0201Q; Lifecycle: Active; Manufacturer: Yageo; Manufacturer_PN: RC0201JR-075K1L; Operating_Temp: -55°C ~ 125°C; Package: 0201; Part_Status: Unrel; Rating: 1/20W; Tolerance: 5%
R7 = RES: RES, 100K OHM, 1%, 1/20W, 0201; Approved: Approved; CY_PN: 500-61334-01; Device_File: 500-61334-01; FPLIST: RESC0603_0201N,RESC0603_0201Q; Lifecycle: Active; Manufacturer: Yageo; Manufacturer_PN: RC0201FR-07100KL; Operating_Temp: -55°C ~ 125°C; Package: 0201; Part_Status: Unrel; Rating: 1/20W; Tolerance: 1%
R159 = RES: RES, FIXED, 100 OHM, 5%, 1/20W, 0201; Approved: Approved; CY_PN: 500-61324-01; Device_File: 500-61324-01; FPLIST: RESC0603_0201N,RESC0603_0201Q; Lifecycle: Active; Manufacturer: Yageo; Manufacturer_PN: RC0201JR-07100RL; Operating_Temp: -55°C ~ 125°C; Package: 0201; Part_Status: In Des; Rating: 1/20W; Tolerance: 5%
TP1-TP10 TP12 TP16-TP20 TP47-TP52 = TP_SMD: TestPoint, PCB, Circle, 0.75mm, SMD; Approved: Approved; CY_PN: NA; DNI: DNI; Device_File: NA; Lifecycle: NA; Manufacturer: NA; Manufacturer_PN: NA; Part_Status: NA
U19 U30 U36 = ESD-ESD7L_SESD7L: DIO, ESD Protection, 5.0V, 2CH, +/-10KV, SOT-723; Approved: Approved; CY_PN: 530-60330-01; Device_File: 530-60330-01; Lifecycle: Active; Manufacturer: onsemi; Operating_Temp: -55°C ~ 150°C; Package: SOT-723; Part_Status: Unrel; Rating: 150mW; Voltage: 5V
U21 = IC_TUSB321_0: IC, USB, TYPE-C, INTERFACE ,SPECIALIZED, 12X2QFN; Approved: Approved; CY_PN: 455-60093-01; Device_File: 455-60093-01; Lifecycle: Active; Manufacturer: Texas Instruments; Operating_Temp: 0??+70?; Operating_Voltage: 4.5V ~ 5.5V; Package: 12-XFQFN; Part_Status: Unrel
D11 LED2 = DIO-LED: LED, BLUE, CLEAR, 470nm, 140mcd, 3.2V, 0402; Approved: Approved; CY_PN: 534-60172-01; Device_File: 534-60172-01; Lifecycle: Active; Manufacturer: Wurth; Operating_Temp: -40°C ~ 85°C; Package: 0402; Part_Status: Unrel; Rating: 20mA; Voltage: 3.2V
D14 = DIO-LED: LED, RED, CLEAR, 624nm, 110mcd, 2V, 0402; Approved: Approved; CY_PN: 534-60171-01; Device_File: 534-60171-01; Lifecycle: Active; Manufacturer: Wurth; Operating_Temp: -40°C ~ 85°C; Package: 0402; Part_Status: Unrel; Rating: 20mA; Voltage: 2V
Q3 = FET-MOS-N-G2S1D6-5G4S3D: FET, MOSFET, 2N-CH, 20V, 0.88A, SOT363; Approved: Approved; Current: 0.88A; Lifecycle: Active; Manufacturer: Infineon; Operating_Temp: -55°C to 150°C; Package: PG-SOT-363; Part_Status: In Prod; Power: 0.5W; Voltage: 20V
R73 R174 R190 R210 = RES: RES, 1K OHM, 1%, 1/20W, 0201; Approved: Approved; CY_PN: 500-61336-01; Device_File: 500-61336-01; FPLIST: RESC0603_0201N,RESC0603_0201Q; Lifecycle: Active; Manufacturer: Yageo; Manufacturer_PN: RC0201FR-071KL; Operating_Temp: -55°C ~ 125°C; Package: 0201; Part_Status: Unrel; Rating: 1/20W; Tolerance: 1%
R189 R219 = RES: RES, Fixed, 10K OHM, 5%, 1/20W, 0201; Approved: Approved; CY_PN: 500-61158-01; Device_File: 500-61158-01; FPLIST: RESC0603_0201N,RESC0603_0201Q; Lifecycle: Active; Manufacturer: Walsin; Manufacturer_PN: WR02X103 JAL; Operating_Temp: -55°C ~ 155°C; Package: 0201; Part_Status: In Des; Rating: 1/20W; Tolerance: 5%
U15 = IC_XC8111AA018R-G: IC, LOAD SWITCH, IC WITH IDEAL DIODE, 1A, USP-6B06; Approved: Approved; CY_PN: 450-60523-01; Device_File: 450-60523-01; Lifecycle: Active; Manufacturer: Torex; Operating_Temp: -40°C ~ 105°C; Operating_Voltage: 1.5V ~ 6.0V; Package: USP-6B06; Part_Status: Unrel
U23 U26 U27 = IC_XC8114AA016R-G: IC, LOAD SWITCH, IC WITH IDEAL DIODE FUNCTION, DFN1820-6G; Approved: Approved; CY_PN: 450-60534-01; Device_File: 450-60534-01; Lifecycle: Active; Manufacturer: Torex; Operating_Temp: -40°C ~ 105°C; Operating_Voltage: 1.5V ~ 6.0V; Package: DFN1820-6G; Part_Status: Unrel
U31 = IC_74LVC2G14GS: IC, INVERT, SCHMITT, 2CH, 2INP, 6XSON; Approved: Approved; CY_PN: 450-60531-01; Device_File: 450-60531-01; Lifecycle: Active; Manufacturer: Nexperia USA Inc.; Operating_Temp: -40°C ~ 125°C; Operating_Voltage: 1.65V ~ 5.5V; Package: 6-XSON, SOT1202; Part_Status: Unrel
C16 C17 C57 C61 = CAP-NP: CAP, CER, 0.1uF, 10%, X5R, 10V, 0201; Approved: Approved; CY_PN: 510-60777-01; Device_File: 510-60777-01; Dielectric: X5R; FPLIST: CAPC0603_0201N,CAPC0603_0201Q; Lifecycle: Active; Manufacturer: Wurth; Manufacturer_PN: 885012104002; Operating_Temp: -55°C ~ 85°C; Package: 0201; Part_Status: In Prod; Tolerance: 0.1; Voltage: 10V
C21 C30 C197 = CAP-NP: CAP, CER, 10uF, 20%, X5R, 10V, 0402; Approved: Approved; CY_PN: 510-60337-01; Device_File: 510-60337-01; Dielectric: X5R; FPLIST: CAPC1005_0402N,CAPC1005_0402M; Lifecycle: Active; Manufacturer: Wurth; Manufacturer_PN: 885012105022; Operating_Temp: -55°C ~ 85°C; Package: 0402; Part_Status: Unrel; Tolerance: 20%; Voltage: 10V
C27 = CAP-NP: CAP, CER, 330pF, 10%, X7R, 25V, 0201; Approved: Approved; CY_PN: 510-61165-01; Device_File: 510-61165-01; Dielectric: X7R; FPLIST: CAPC0603_0201N,CAPC0603_0201Q; Lifecycle: Active; Manufacturer: Murata; Manufacturer_PN: GRM033R71E331KA01D; Operating_Temp: -55°C ~ 125°C; Package: 0201; Part_Status: Unrel; Tolerance: 10%; Voltage: 25V
C31 = CAP-NP: CAP, CER, 1uF, 20%, 10V, X5R, 0201; Approved: Approved; CY_PN: 510-61183-01; Device_File: 510-61183-01; Dielectric: X5R; FPLIST: CAPC0603_0201N,CAPC0603_0201Q; Lifecycle: Active; Manufacturer: Murata; Manufacturer_PN: GRM033R61A105ME15D; Operating_Temp: -55°C ~ 85°C; Package: 0201; Part_Status: In prod; Tolerance: 20%; Voltage: 10V
C189 C191 C194 C196 = CAP-NP: CAP, CER, 1UF, 20%, 10V, X5R, 0402; Approved: Approved; CY_PN: 510-60877-01; Device_File: 510-60877-01; Dielectric: X5R; FPLIST: CAPC1005_0402N,CAPC1005_0402M; Lifecycle: Active; Manufacturer: Wurth; Manufacturer_PN: 885012105012; Operating_Temp: -55°C ~ 85°C; Package: 0402; Part_Status: In Prod; Tolerance: 20%; Voltage: 10V
L1 = IND-SHIELDED: IND,FIXED, SHIELDED, 1uH, 20%, 4A, 32 mOHM, SMD; Approved: Approved; CY_PN: 520-60347-01; Current: 4A; DB_Status: Verified; Device_File: 520-60347-01; ESR: 32mOhm; Lifecycle: Active; Manufacturer: Würth Elektronik; Manufacturer_PN: 74438336010; Material: shielded; Operating_Temp: -40°C ~ 125°C; Package: SMD; Part_Status: Unrel; Part_Type: Inductor; Tolerance: ±20%
R10 = RES: RES, FIXED, 348K OHM, 1%, 1/20W, 0201; Approved: Approved; CY_PN: 500-61437-01; Device_File: 500-61437-01; FPLIST: RESC0603_0201N,RESC0603_0201Q; Lifecycle: Active; Manufacturer: YAGEO; Manufacturer_PN: RC0201FR-07348KL; Operating_Temp: -55°C ~ 125°C; Package: 0201; Part_Status: unrel; Rating: 1/20W; Tolerance: 1%
R11 R15 = RES: RES, FIXED, 47K OHM, 1%, 1/20W, 0201; Approved: Approved; CY_PN: 500-61438-01; Device_File: 500-61438-01; FPLIST: RESC0603_0201N,RESC0603_0201Q; Lifecycle: Active; Manufacturer: YAGEO; Manufacturer_PN: RC0201FR-0747KL; Operating_Temp: -55°C ~ 125°C; Package: 0201; Part_Status: unrel; Rating: 1/20W; Tolerance: 1%
R16 = RES: RES, 15K OHM, 1%, 1/20W, 0201; Approved: Approved; CY_PN: 500-61327-01; Device_File: 500-61327-01; FPLIST: RESC0603_0201N,RESC0603_0201Q; Lifecycle: Active; Manufacturer: Yageo; Manufacturer_PN: RC0201FR-0715KL; Operating_Temp: -55°C ~ 125°C; Package: 0201; Part_Status: In Des; Rating: 1/20W; Tolerance: 1%
U13 = IC_XCL212B082DR_0: IC, DC DC, CONVERTER, 0.9-6V, 11-PowerLQFN Module; Approved: Approved; CY_PN: 455-60094-01; Device_File: 455-60094-01; Lifecycle: Active; Manufacturer: Torex; Operating_Temp: -40°C ~ 85°C; Operating_Voltage: 2.7V?6.0V; Package: 11-PowerLQFN Module; Part_Status: Unrel
U29 = IC_TPS61022_0: IC, REG, BOOST, ADJ, 0.5V-5.5V, 2.2V-5.5V, 8A, VQFN-7; Approved: Approved; CY_PN: 471-60062-01; Device_File: 471-60062-01; Lifecycle: Active; Manufacturer: Texas Instruments; Operating_Temp: -40°C ~ 125°C; Operating_Voltage: 0.5V ~ 5.5V; Package: VQFN-7; Part_Status: Unrel
U33 = NCP163AMX150TBG: IC, REG LINEAR, 1.8V, 250MA, 4XDFN; Approved: Approved; CY_PN: 471-60071-01; Device_File: 471-60071-01; Lifecycle: Active; Manufacturer: Onsemi; Operating_Temp: -40°C ~ 125°C; Operating_Voltage: 2.2V ~ 5.5V; Package: 4-XDFN Exposed Pad; Part_Status: Unrel
U34 = IC_XCL240B183FR-G_0: IC, DC DC, CONVERTER, STEP DOWN, 1A, CL-2025-02; Approved: Approved; CY_PN: 455-60097-01; Device_File: 455-60097-01; Lifecycle: Active; Manufacturer: Torex; Operating_Temp: -40°C ~ 105°C; Operating_Voltage: 2.5V ~ 5V; Package: CL-2025-02; Part_Status: Unrel
U35 = NCP163AMX150TBG: IC, REG LINEAR, 3.3V, 250MA, 4XDFN; Approved: Approved; CY_PN: 471-60069-01; Device_File: 471-60069-01; Lifecycle: Active; Manufacturer: Onsemi; Operating_Temp: -40°C ~ 125°C; Operating_Voltage: 2.2V ~ 5.5V; Package: 4-XDFN Exposed Pad; Part_Status: Unrel
C35 C37 C39 C41 C43 C44 C46 C48 C50 C52-C54 = CAP-NP: CAP, CER, 1uF, 20%, 10V, X5R, 0201; Approved: Approved; CY_PN: 510-61183-01; Device File: 510-60276-01; Device_File: 510-61183-01; Dielectric: X5R; FPLIST: CAPC0603_0201N,CAPC0603_0201Q; Lifecycle: Active; Manufacturer: Murata; Manufacturer_PN: GRM033R61A105ME15D; Operating_Temp: -55°C ~ 85°C; Package: 0201; Part Status: In Prod; Part_Status: In prod; Tolerance: 20%; Voltage: 10V
R18 R218 = RES: RES, FIXED, 0 OHM, JUMPER, 1A, 1/16W, 0402; Approved: Approved; CY_PN: 500-60344-01; Device File: 500-60037-01; Device_File: 500-60344-01; FPLIST: RESC1005_0402N,RESC1005_0402M; Lifecycle: Active; Manufacturer: Wurth; Manufacturer_PN: 560112110001; Operating_Temp: -55°C ~ 155°C; Package: 0402; Part_Status: In Prod; Rating: 1/16W; Tolerance: JUMPER
R21 = RES: RES, 49.9K OHM, 1%, 1/20W, 0201; Approved: Approved; CY_PN: 500-61326-01; Device File: 500-60149-01; Device_File: 500-61326-01; FPLIST: RESC0603_0201N,RESC0603_0201Q; Lifecycle: Active; Manufacturer: Yageo; Manufacturer_PN: RC0201FR-0749K9L; Operating_Temp: -55°C ~ 125°C; Package: 0201; Part_Status: Unrel; Rating: 1/20W; Tolerance: 1%
R22 = RES: RES, 49.9K OHM, 1%, 1/20W, 0201; Approved: Approved; CY_PN: 500-61326-01; DNI: DNI; Device File: 500-60149-01; Device_File: 500-61326-01; FPLIST: RESC0603_0201N,RESC0603_0201Q; Lifecycle: Active; Manufacturer: Yageo; Manufacturer_PN: RC0201FR-0749K9L; Operating_Temp: -55°C ~ 125°C; Package: 0201; Part_Status: Unrel; Rating: 1/20W; Tolerance: 1%
R23 R25 = RES: RES, 15K OHM, 1%, 1/20W, 0201; Approved: Approved; CY_PN: 500-61327-01; Device File: 500-60868-01; Device_File: 500-61327-01; FPLIST: RESC0603_0201N,RESC0603_0201Q; Lifecycle: Active; Manufacturer: Yageo; Manufacturer_PN: RC0201FR-0715KL; Operating_Temp: -55°C ~ 125°C; Package: 0201; Part_Status: Unrel; Rating: 1/20W; Tolerance: 1%
R24 R27 = RES: RES, 30K OHM, 1%, 1/20W, 0201; Approved: Approved; CY_PN: 500-61325-01; Device File: 500-60558-01; Device_File: 500-61325-01; FPLIST: RESC0603_0201N,RESC0603_0201Q; Lifecycle: Active; Manufacturer: Yageo; Manufacturer_PN: RC0201FR-0730KL; Operating_Temp: -55°C ~ 125°C; Package: 0201; Part_Status: Unrel; Rating: 1/20W; Tolerance: 1%
R26 R28 = RES: RES, 22 OHM, 5%, 1/20W, 0201; Approved: Approved; CY_PN: 500-61328-01; Device File: 500-60085-01; Device_File: 500-61328-01; FPLIST: RESC0603_0201N,RESC0603_0201Q; Lifecycle: Active; Manufacturer: Yageo; Manufacturer_PN: RC0201JR-0722RL; Operating_Temp: -55°C ~ 125°C; Package: 0201; Part_Status: Unrel; Rating: 1/20W; Tolerance: 5%
R29 = RES: RES, 4.7K OHM, 5%, 1/20W, 0201; Approved: Approved; CY_PN: 500-60979-01; Device File: 500-60095-01; Device_File: 500-60979-01; FPLIST: RESC0603_0201N,RESC0603_0201Q; Lifecycle: Active; Manufacturer: Yageo; Manufacturer_PN: RC0201JR-074K7L; Operating_Temp: -55°C ~ 125°C; Package: 0201; Part_Status: Unrel; Rating: 1/20W; Tolerance: 5%
R30 R157 = RES: RES, FIXED, 560 OHM, 5%, 100PPM, 1/10W, 0402; Approved: Approved; CY_PN: 500-61393-01; Device_File: 500-61393-01; FPLIST: RESC1005_0402N,RESC1005_0402M; Lifecycle: Active; Manufacturer: Wurth; Manufacturer_PN: 560112110037; Operating_Temp: -55°C ~ 155°C; Package: 0402; Part_Status: unrel; Rating: 1/10W; Tolerance: 5%
R31 R32 R209 = RES: RES, 2.2K OHM, 5%, 1/20W, 0201; Approved: Approved; CY_PN: 500-61329-01; Device File: 500-60095-01; Device_File: 500-61329-01; FPLIST: RESC0603_0201N,RESC0603_0201Q; Lifecycle: Active; Manufacturer: Yageo; Manufacturer_PN: RC0201JR-072K2L; Operating_Temp: -55°C ~ 125°C; Package: 0201; Part_Status: Unrel; Rating: 1/20W; Tolerance: 5%
SW1 SW3 = SWITCH-PB-12-34: SW, Tactile Switch, SPST-NO, TOP Actuated, White, 16V, 0.05A, SMD; Actuator_Length: 2.5mm; Approved: Approved; CY_PN: 770-60033-01; Circuit: SPST-NO; Current_Rating: 0.05A; Device File: 770-60033-01; Lifecycle: Active; Manufacturer: Wurth; Operating_Force: 260gf; Operating_Temp: -40°C ~ 85°C; Part_Status: In Prod; Pins: 4; Switch_Function: Off-Mom
U2 = CY8C5868LTI-LP039: IC, CYPRESS, MCU, PSoC 5LP, 32 Bit MCU, 67MHz, 1.8V-5.5V, 68-QFN; Description1: 64KB SRAM, 256KB Flash, 2KB EEPROM, 20-bit Del-Sig, 2x12-bit SAR, 24UDBs, FS USB, CAN, 38 GPIO, 8 SIO; FPLIST: QFN40P800X800X100-69M,QFN40P800X800_68-H580N; Lifecycle: Active; Manufacturer: Cypress; Operating_Temp: -40°C to 85°C; Operating_Voltage: 1.8V-5.5V; Package: 68-QFN; Part_Status: In Prod
C55 C56 = CAP-NP: CAP, CER, 0201, 10pF, 2%, 25V, C0G; Approved: Approved; CY_PN: 510-60964-01; Device_File: 510-60964-01; Dielectric: C0G; FPLIST: CAPC0603_0201N,CAPC0603_0201Q; Lifecycle: Active; Manufacturer: Murata; Manufacturer_PN: GRM0335C1E100GA01D; Operating_Temp: -55°C ~ 125°C; Package: 0201; Part_Status: Unrel; Tolerance: 2%; Voltage: 25V
C59 C60 = CAP-NP: CAP, CER, 22pF, 5%, C0G, 25V, 0201; Approved: Approved; CY_PN: 510-60833-01; Device_File: 510-60833-01; Dielectric: C0G; FPLIST: CAPC0603_0201N,CAPC0603_0201Q; Lifecycle: Active; Manufacturer: Murata; Manufacturer_PN: GRM0335C1E220JA01D; Operating_Temp: -55°C ~ 125°C; Package: 0201; Part_Status: In Prod; Tolerance: 5%; Voltage: 25V
D4 = DIO-TVS: DIO, TVS, UNIDIR, 5V, 18.6V, 174W, SOD-523; CY_PN: 530-60165-01; Device File: 530-60165-01; Device_File: 530-60165-01; Lifecycle: Active; Manufacturer: MCC; Operating_Temp: -55°C to 150°C; Package: SOD-523; Part_Status: In Prod; Rating: 174W; Voltage: 5V
J4 = PLG-10-ODD-EVEN-J: CONN, HDR, MALE, DUAL, 10POS, 1.27mm, GOLD, STR, SMD; CY_PN: 710-60030-01; Conatct_Length: 3.05mm; Contact_Finish: GOLD; Current_Rating: 3.4A; DNI: DNI; Device_File: 710-60030-01; Lifecycle: Active; Manufacturer: Samtec; Manufacturer_PN: FTSH-105-01-L-DV-K-P-TR; Mated_Height: 5.97mm; Operating_Temp: -55°C to 125°C; Part_Status: In Prod; Pin_Pitch: 1.27; Pins: 10; Row_pitch: 1.27; Rows: 2; Shrouding: Shrouded
LED1 = DIO-LED: LED, GREEN, CLEAR, 520nm, 750mcd, 3.3V, 0402; Approved: Approved; CY_PN: 534-60170-01; Device_File: 534-60170-01; Lifecycle: Active; Manufacturer: Wurth; Operating_Temp: -40°C ~ 85°C; Package: 0402; Part_Status: Unrel; Rating: 20mA; Voltage: 3.3V
LED3 = LED_150066M153000: LED, RGB, DIFFUSED, 2V Red, 3.3V Green, 3.3V Blue, SMD, 0606; Approved: Approved; CY_PN: 534-60173-01; Device_File: 534-60173-01; Lifecycle: Active; Manufacturer: Wurth; Operating_Temp: -40°C ~ 85°C; Package: 0606; Part_Status: Unrel; Rating: 20mA; Voltage: 2V, 3.3V, 3.3V
Q7-Q11 = FET-MOS-N_XP222N03017R: MOSFET, N-CH, 20V, 300mA, SOT-723; Approved: Approved; CY_PN: 532-60103-01; Current: 300mA; Device_File: 532-60103-01; Lifecycle: Active; Manufacturer: Torex; Operating_Temp: -55°C ~ 150°C; Package: SOT-723; Part_Status: Unrel; Power: 350mW; Voltage: 20V
R72 = RES: RES, 4.7K OHM, 5%, 1/20W, 0201; Approved: Approved; CY_PN: 500-60979-01; Device_File: 500-60979-01; FPLIST: RESC0603_0201N,RESC0603_0201Q; Lifecycle: Active; Manufacturer: Yageo; Manufacturer_PN: RC0201JR-074K7L; Operating_Temp: -55°C ~ 125°C; Package: 0201; Part_Status: Unrel; Rating: 1/20W; Tolerance: 5%
R156 = RES: RES, Fixed, 470 OHM, 1%, 1/10W, 0402; Approved: Approved; CY_PN: 500-61405-01; Device_File: 500-61405-01; FPLIST: RESC1005_0402N,RESC1005_0402M; Lifecycle: Active; Manufacturer: Wurth; Manufacturer_PN: 560112110167; Operating_Temp: -55°C ~ 155°C; Package: 0402; Part_Status: unrel; Rating: 1/10W; Tolerance: 1%
R165 = RES: RES, Fixed, 150 OHM, 1%, 1/10W, 0402; Approved: Approved; CY_PN: 500-60730-01; Device_File: 500-60730-01; FPLIST: RESC1005_0402N,RESC1005_0402M; Lifecycle: Active; Manufacturer: Wurth; Manufacturer_PN: 560112110061; Operating_Temp: -55°C ~ 155°C; Package: 0402; Part_Status: In Prod; Rating: 1/10W; Tolerance: 1%
R187 = RES: RES, Fixed, 0 OHM, JUMPER, 1/10W, 0603; Approved: Approved; CY_PN: 500-60037-01; DNI: DNI; Device_File: 500-60037-01; FPLIST: RESC1608_0603N,RESC1608_0603Q,RESC1608_0603M; Lifecycle: Active; Manufacturer: Wurth; Manufacturer_PN: 560112116001; Operating_Temp: -55°C ~ 155°C; Package: 0603; Part_Status: In Prod; Rating: 1/10W; Tolerance: JUMPER
R188 = RES: RES, Fixed, 0 OHM, JUMPER, 1/10W, 0603; Approved: Approved; CY_PN: 500-60037-01; Device_File: 500-60037-01; FPLIST: RESC1608_0603N,RESC1608_0603Q,RESC1608_0603M; Lifecycle: Active; Manufacturer: Wurth; Manufacturer_PN: 560112116001; Operating_Temp: -55°C ~ 155°C; Package: 0603; Part_Status: In Prod; Rating: 1/10W; Tolerance: JUMPER
R198 = RES: RES, 4.7K OHM, 5%, 1/20W, 0201; Approved: Approved; CY_PN: 500-60979-01; DNI: DNI; Device_File: 500-60979-01; FPLIST: RESC0603_0201N,RESC0603_0201Q; Lifecycle: Active; Manufacturer: Yageo; Manufacturer_PN: RC0201JR-074K7L; Operating_Temp: -55°C ~ 125°C; Package: 0201; Part_Status: Unrel; Rating: 1/20W; Tolerance: 5%
R199-R202 = RES: RES, Fixed, 10K OHM, 5%, 1/20W, 0201; Approved: Approved; CY_PN: 500-61158-01; DNI: DNI; Device_File: 500-61158-01; FPLIST: RESC0603_0201N,RESC0603_0201Q; Lifecycle: Active; Manufacturer: Walsin; Manufacturer_PN: WR02X103 JAL; Operating_Temp: -55°C ~ 155°C; Package: 0201; Part_Status: In Des; Rating: 1/20W; Tolerance: 5%
SW2 = SWITCH-PB-12-34: SW, Tactile Switch, SPST-NO, TOP Actuated, Black, 16V, 0.05A, SMD; Actuator_Length: 2.5mm; Approved: Approved; CY_PN: 770-60115-01; Circuit: SPST-NO; Current_Rating: 0.05A; Device File: 770-60115-01; Lifecycle: Active; Manufacturer: Wurth; Operating_Force: 160gf; Operating_Temp: -40°C ~ 85°C; Part_Status: In Prod; Pins: 4; Switch_Function: Off-Mom
Y1 = XTAL-4P-2G4G: XTAL, 17.2032MHz, 10ppm, 10pF,SMD; Approved: Approved; CY_PN: 542-60074-01; Description1: 2.00mm x 1.60mm x 0.5mm; Device_File: 542-60074-01; Frequency_Stability: NA; Lifecycle: Active; Load_Capacitance: 10pF; Manufacturer: TXC Corporation; Manufacturer_PN: 8Y17270001; Operating_Temp: -40°C ~ 85°C; Output_Type: NA; Package: SMD; Part_Status: In Prod; Supply_Voltage: NA; Tolerance: 10ppm
Y2 = XTAL-2P: XTAL, 32.768kHz, 20ppm, 12.5pF, SMD; Approved: Approved; CY_PN: 542-60070-01; Description 2: 1.60mm x 1.00mm x 0.5mm; Description1: 1.60mm x 1.00mm x 0.5mm; Device File: 542-60070-01; Device_File: 542-60070-01; Frequency_Stability: NA; Lifecycle: Active; Load_Capacitance: 12.5pF; Manufacturer: TXC Corporation; Manufacturer_PN: 9H03277001; Operating_Temp: -40°C ~ 85°C; Output_Type: NA; Package: SMD; Part_Status: In Prod; Supply_Voltage: NA; Tolerance: 20ppm
Y3 = ECS-2520MV: OSC XO 24.0000MHZ CMOS SMD 20ppm; Approved: Approved; CY_PN: 540-60025-01; Description1: 2.50mm x 2.00mm x 0.90mm; Device_File: 540-60025-01; Frequency_Stability: NA; Lifecycle: Active; Load_Capacitance: 15pF; Manufacturer: ECS Inc; Manufacturer_PN: ECS-2520MV-240-DN-TR; Operating_Temp: -40°C ~ 85°C; Output_Type: NA; Package: SMD; Part_Status: In Des; Supply_Voltage: NA; Tolerance: 20ppm
ACC6-ACC9 = STANDOFF_NON_PLATED: HW, STANDOFF, NYLON, Height 6.17mm, inner dia-2.1mm, outer dia-4mm; CY_PN: 702-60044-01; Manufacturer: Wurth; Operating_Temp: -30°C to 85°C; Part_Status: unrel
ACC10 = LBL_QR_Code: LBL, QR CODE, 10mm x 10mm, PSOC Edge E84 AI Board; Manufacturer: Infineon Approved CM; Manufacturer_PN: NA; Operating_Temp: NA; Part_Status: unrel
ACC11 = LABEL: LBL, PCA Label, Vendor Code, Datecode, Serial Number (YYWWVVXXXXX); CY_PN: 899-60120-01; Device File: 899-60120-01; Manufacturer: JETech; Manufacturer_PN: 899-60120-01

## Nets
GND_EARTH: C13.1 J1.SH1 J1.SH2 J1.SH3 J1.SH4 J2.SH1 J2.SH2 J2.SH3 J2.SH4 R7.1
GND_SIGNAL: C1.1 C3.1 C4.1 C5.1 C6.1 C7.1 C8.1 C9.1 C11.1 C12.2 C13.2 C14.2 C16.2 C17.2 C21.2 C28.2 C30.2 C31.2 C35.2 C36.2 C37.2 C38.2 C39.2 C40.2 C41.2 C42.2 C43.2 C44.2 C45.2 C46.2 C47.2 C48.2 C49.2 C50.2 C51.2 C52.2 C53.2 C54.2 C55.2 C56.2 C57.2 C58.2 C59.1 C60.1 C61.2 C182.2 C183.2 C184.2 C185.2 C186.2 C189.2 C191.2 C194.2 C196.2 C197.2 D1.A(ANODE) D2.A(ANODE) D4.A(ANODE) D15.A(ANODE) J1.A1(GND_1) J1.A12(GND_2) J1.B1(GND_3) J1.B12(GND_4) J2.A1(GND_1) J2.A12(GND_2) J2.B1(GND_3) J2.B12(GND_4) J3.2 J3.SH1 J3.SH2 J4.3 J4.5 J4.7 J4.9 LED4.K(CATHODE) LED5.K(CATHODE) Q3.1(S) Q3.4(S) Q7.S Q8.S Q9.S Q10.S Q11.S R3.2 R4.2 R7.2 R11.2 R16.2 R22.1 R24.1 R27.1 R73.1 R173.1 R187.1 R191.1 R211.1 R212.1 R213.1 R214.1 R215.1 SW2.3 SW2.4 SW3.3 SW3.4 TP2.1(TP) TP10.1(TP) TP17.1(TP) TP47.1(TP) U2.5(VSSB) U2.7(VBOOST) U2.8(VBAT) U2.9(VSSD) U2.25(VSSD) U2.43(VSSA) U2.45(VSSD) U2.58(VSSD) U2.62(P2[0]) U2.63(P2[1]) U2.H(EPAD) U13.8(GND) U15.3(VSS) U15.H(EPAD) U19.3(A) U21.10(GND) U23.3(VSS) U23.H(EPAD) U26.3(VSS) U26.H(EPAD) U27.3(VSS) U27.H(EPAD) U29.1(GND) U29.6(MODE) U30.3(A) U31.2(GND) U33.2(GND) U33.5(EPAD) U34.2(AGND) U34.5(PGND) U34.H(EPAD) U35.2(GND) U35.5(EPAD) U36.3(A) Y1.2(GND_1) Y1.4(GND_2) Y3.2(GND) ; also on sheet 10 11 12 13 14 15 16 17 20 21
VBAT_IN: C9.2 C186.1 D15.K(CATHODE) J3.1 TP8.1(TP) U23.4(EN) U23.6(VIN)
VCC_1V8: C196.1 TP50.1(TP) U33.1(OUT) ; also on sheet 11 13 16 21
VCC_3V3: C191.1 TP51.1(TP) U35.1(OUT) ; also on sheet 11 13
VCC_IN: C3.2 C7.2 C8.2 C14.1 C16.1 L1.1 U23.1(VOUT) U26.1(VOUT) U27.1(VOUT) U29.5(EN) U29.7(VIN)
VDD_1V8: C5.2 C61.1 C197.1 R2.1 R5.2 R6.1 R8.2 R9.1 TP49.1(TP) U31.5(VCC) U34.3(VOUT) U34.8(L2) Y3.1(Tri-State) Y3.4(VDD) ; also on sheet 10 12 13 14 15 16 21
VDD_3V3: C27.1 C28.1 C194.1 R15.1 R159.2 R188.2 TP48.1(TP) U13.11(L2) U33.3(EN) U33.4(IN) ; also on sheet 12 13 15 17 21
VDD_5V: C6.2 C12.1 C17.1 C21.1 C30.1 C31.1 C182.1 C183.1 C184.1 C189.1 LED3.4(COM) R10.1 R174.2 R190.2 R209.2 R210.2 TP12.1(TP) U13.6(CE) U13.7(AVIN) U13.9(PVIN) U15.6(VIN) U21.12(VDD) U29.3(VOUT) U34.4(EN) U34.6(VIN) U35.3(EN) U35.4(IN) ; also on sheet 13 15 17
BOOT: R189.1 ; also on sheet 19
ECO_IN: C55.1 Y1.1 ; also on sheet 19
ECO_OUT: C56.1 Y1.3 ; also on sheet 19
EXT_CLK: R218.2 ; also on sheet 19
I2C_SCL_1V8: R32.1 U2.38(P12[0]) ; also on sheet 10 15 19
I2C_SDA_1V8: R31.1 U2.39(P12[1]) ; also on sheet 10 15 19
KP_USB_DM: J1.A7(DN1) J1.B7(DN2) R28.1 U19.1(K1)
KP_USB_DP: J1.A6(DP1) J1.B6(DP2) R26.1 U19.2(K2)
KP_VBUS: C4.2 D1.K(CATHODE) J1.A4(VBUS_1) J1.A9(VBUS_2) J1.B4(VBUS_3) J1.B9(VBUS_4) R18.2 TP1.1(TP) U27.4(EN) U27.6(VIN)
MCU_UART_RX_KP3_TX: U2.20(P12[6]) ; also on sheet 19
MCU_UART_TX_KP3_RX: R29.1 U2.21(P12[7]) ; also on sheet 19
P5LP1_2: SW3.1 SW3.2 U2.13(P1[2])
P5LP1_4: R30.2 U2.15(P1[4])
P5LP2_2: U2.64(P2[2])
P5LP2_3: U2.65(P2[3])
P5LP2_4: U2.66(P2[4])
P5LP_SIO_VREF: R21.2 R22.2 U2.48(P0[0])
P5LP_SWCLK: TP19.1(TP) U2.12(P1[1])
P5LP_SWDIO: TP20.1(TP) U2.11(P1[0])
P5LP_VCCD: C44.1 C45.1 U2.26(VCCD) U2.57(VCCD)
P5LP_VDD: C35.1 C36.1 C37.1 C38.1 C39.1 C40.1 C41.1 C42.1 C46.1 C47.1 C48.1 C49.1 C50.1 C51.1 R18.1 R25.1 TP16.1(TP) U2.17(VDDIO1) U2.24(VDDD) U2.35(VDDIO3) U2.44(VDDA) U2.52(VDDIO) U2.59(VDDD) U2.67(VDDIO2)
P5LP_XRES: TP18.1(TP) U2.10(~{XRES})
PE84_RST_L: C58.1 J4.10 R72.2 SW2.1 SW2.2 U2.3(P12[4]) ; also on sheet 19
PE84_SWCLK: J4.4 R200.2 U2.47(P12[3]) ; also on sheet 19
PE84_SWDIO: J4.2 R199.2 U2.46(P12[2]) ; also on sheet 19
PE84_SWO: J4.6 R201.2 ; also on sheet 19
PE84_TDI: J4.8 R202.2 ; also on sheet 19
PE84_USB_CC1: J2.A5(CC1) U21.1(CC1) U36.1(K1)
PE84_USB_CC2: J2.B5(CC2) U21.2(CC2) U36.2(K2)
PE84_USB_CF: R2.2 TP3.1(TP) U21.6(\~{VCONN_FAULT}) ; also on sheet 19
PE84_USB_DIR: R6.2 TP5.1(TP) U21.11(DIR) ; also on sheet 19
PE84_USB_DM: J2.A7(DN1) J2.B7(DN2) U30.1(K1) ; also on sheet 19
PE84_USB_DP: J2.A6(DP1) J2.B6(DP2) U30.2(K2) ; also on sheet 19
PE84_USB_ID: R9.2 TP7.1(TP) U21.9(ID) U31.1(A) ; also on sheet 19
PE84_USB_OUT1: R8.1 TP6.1(TP) U21.7(OUT1) ; also on sheet 19
PE84_USB_OUT2: R5.1 TP4.1(TP) U21.8(OUT2) ; also on sheet 19
PE84_VBUS: C1.2 C11.2 C185.1 D2.K(CATHODE) J2.A4(VBUS_1) J2.A9(VBUS_2) J2.B4(VBUS_3) J2.B9(VBUS_4) R1.2 R219.2 TP9.1(TP) U15.1(VOUT) U26.6(VIN)
PE84_VTARG: C54.1 D4.K(CATHODE) J4.1 R21.1 R23.1 R29.2 R31.2 R32.2 R72.1 R198.1 R199.1 R200.1 R201.1 R202.1 ; also on sheet 20 21
USB_DEV_EN: Q3.5(G) R191.2 R219.1 U26.4(EN) U31.4(Y)
USB_HOST_EN: Q3.2(G) R173.2 U15.4(CE) U31.3(A) U31.6(Y)
USB_V_SENSE: R25.2 R27.2 U2.19(P1[7])
USER_BTN: C57.1 R198.2 SW1.1 SW1.2 ; also on sheet 19
USER_LED1: Q7.G R211.2 ; also on sheet 19
USER_LED2: Q8.G R212.2 ; also on sheet 19
USER_LED_RGB_B: Q11.G R215.2 ; also on sheet 19
USER_LED_RGB_G: Q10.G R214.2 ; also on sheet 19
USER_LED_RGB_R: Q9.G R213.2 ; also on sheet 19
USR_RGB_B: Q11.D R165.2
USR_RGB_G: Q10.D R157.1
USR_RGB_R: Q9.D R156.1
VTARG_MEAS: R23.2 R24.2 U2.32(P3[3])
WCO_IN: C60.2 Y2.1 ; also on sheet 19
WCO_OUT: C59.2 Y2.2 ; also on sheet 19
N17489317: R73.2 SW1.3 SW1.4
N17580471: C43.1 U2.53(P0[4])
N17581080: C52.1 U2.42(VCCA)
N17581130: R26.2 U2.22(P15[6]_D+)
N17581131: R28.2 U2.23(P15[7]_D-)
N17581135: C53.1 U2.31(P3[2])
N17606878: LED4.A(ANODE) R30.1
N17713209: L1.2 U29.2(SW)
N17713383: R10.2 R11.1 U29.4(FB)
N17787194: J1.A5(CC1) R4.1
N17787196: J1.B5(CC2) R3.1
N17852597: R1.1 U21.5(VBUS_DET)
N17861601: LED5.A(ANODE) R159.1
N17865809: U13.2(LX_1) U13.3(LX_2) U13.10(L1)
N17865831: C27.2 R15.2 R16.1 U13.5(FB)
N17879800: U34.1(LX) U34.7(L1)
N17892556: R218.1 TP52.1(TP) Y3.3(Output)
N17899696: R187.2 R188.1 R189.2
N17936697: D11.A(ANODE) R174.1
N17936707: D11.K(CATHODE) Q3.6(D1)
N17937120: D14.A(ANODE) R190.1
N17937130: D14.K(CATHODE) Q3.3(D1)
N18038435: LED1.A(ANODE) R209.1
N18038437: LED2.A(ANODE) R210.1
N18038455: LED1.K(CATHODE) Q7.D
N18038457: LED2.K(CATHODE) Q8.D
N18039037: LED3.1(RED) R156.2
N18039056: LED3.2(GRN) R157.2
N18039072: LED3.3(BLU) R165.1

Not connected (* = marked no-connect by the designer): J1 A8(SBU1)* B8(SBU2)*; J2 A8(SBU1)* B8(SBU2)*; U2 1(P2[6])* 2(P2[7])* 4(P12[5])* 6(IND)* 14(P1[3])* 16(P1[5])* 18(P1[6])* 27(P15[0])* 28(P15[1])* 29(P3[0])* 30(P3[1])* 33(P3[4])* 34(P3[5])* 36(P3[6])* 37(P3[7])* 40(P15[2])* 41(P15[3])* 49(P0[1])* 50(P0[2])* 51(P0[3])* 54(P0[5])* 55(P0[6])* 56(P0[7])* 60(P15[4])* 61(P15[5])* 68(P2[5])*; U13 1(NC1)* 4(NC2)*; U15 2(NC1)* 5(NC2)*; U21 3(CURRENT_MODE)* 4(PORT)*; U23 2(NC1)* 5(NC2)*; U26 2(NC1)* 5(NC2)*; U27 2(NC1)* 5(NC2)*

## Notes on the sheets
sheet 1
- Accessories
- QR Code
- PCBA Label
- Nylon Standoffs
sheet 2
- KIT_PSE84_AI - PSOC™ Edge E84 AI Board
- CONTENTS
- PAGE
- DESCRIPTION
- 01
- Title, Table of Contents & Drawing Numbers
- 02
- Function Block Diagram
- 03
- Power Block Diagram
- 04
- USB and Battery Power Supply Inputs
- 05
- Power supply OR'ing and USB-C Port Controller
- 06
- Regulated Voltage Supply section
- 07
- KitProg3 Interface
- 08
- On-board Peripherals
- 09
- On board Sensors
- 10
- RADAR Sensor Interface
- 11
- 2YF WiFi / BLE Module Interface
- 12
- IO Expansion connectors
- 13
- Flash Memory and RAM Interface
- 14
- Audio Class-D Amplifier Interface
- 15
- Analog Microphones Interface
- 16
- MIPI-DSI Display Interface
- 17
- PSOC™ Edge E84 Power1
- 18
- PSOC™ Edge E84 Power2
- 19
- PSOC™ Edge E84 I/O Signals
- 20
- Accessories
- 21
- Revision History
- Drawing Numbers
- PCBA
- PCB
- FAB DRW
- ASSY DRW
- SCH DRW
sheet 5
- USB-C Host enable
- USB-C Host/Device Status LED's
- USB-C device enable and Ideal Diode Power OR'ing
sheet 6
- KitProg3 USB Interface and Power Supply
- PSOC™ Edge E84 USB Device/Host Interface
- Battery  input  Connector
- Power LED
- Amber
- USB-C DRP controller
- ID Signal
- PORT MODE
- HIGH (1.8V)
- UFP
- LOW (0V)
- DFP or DRP as DFP
- NOTE:
- Type-C current is in default value (500mA)
  in DFP port mode as CURRENT_MODE
  pin left un-connected
sheet 7
- 5V Boost Voltage Regulator
- 1.8V Buck Voltage Regulator
- 2.5V~5V, 3A
- 5V, 3A
- 3.3V Linear Voltage Regulator
- 3.3V, 150mA
- 3.3V Buck Voltage regulator
- 3.3V, 2A
- 1.8V Linear Voltage Regulator
- 1.8V, 250mA
sheet 8
- Decoupling Capacitors
- PSOC™ 5LP based KitProg3
- PSOC™ 5LP Power
- SAR Bypass
  Capacitor
- Voltage Monitoring
- PSOC™ 5LP Programming Header
- Note:
- This is used for programing on board PSOC™ 5LP
  with KitProg3 firmware
- KitProg3 UART RX Pull Up
- KP3_UART_TX
- KP3_UART_RX
- Del-Sig Bypass Capacitor
- KitProg3 H/W Revision
- KitProg3 Mode Switch
- KitProg3 Status LED
- I2C Pull Ups
- Bit 0
- Bit 1
- Bit 2
- Amber
- Bit 3
- Bit 4
- ID = 0x03
- GND is read as binary "1" and
  floating as "0"
- Note:
sheet 9
- ECO
- External Oscillator
- User LED's
- WCO
- PSOC™ Edge E84 SWD/JTAG Header
- TMS/SWDIO
- TCK/SWCLK
- TDO/SWO
- TDI
- XRES
- NOTE:
- Active High driven USER LED's
- User Button
- Reset Switch
- RGB User LED
- BOOT Configuration
- Make Y-connection
- BOOT CONFIGURATION:
- BOOT
- 0
- BOOT LOCATION
- OEM_APP
- 1
- OEM_ALT_APP
- NOTE:
- BOOT = 1 by default.
- SWD/JTAG Pull up's
- NOTE:
- Active Low driven RGB LED's
